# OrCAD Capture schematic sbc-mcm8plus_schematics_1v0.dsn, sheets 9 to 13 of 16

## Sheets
9 04. ENET-RTL8211, ENET1-RGMII: size A3; title: SBC-MCM8PLUS   04. ENET-RTL8211, ENET1-RGMII
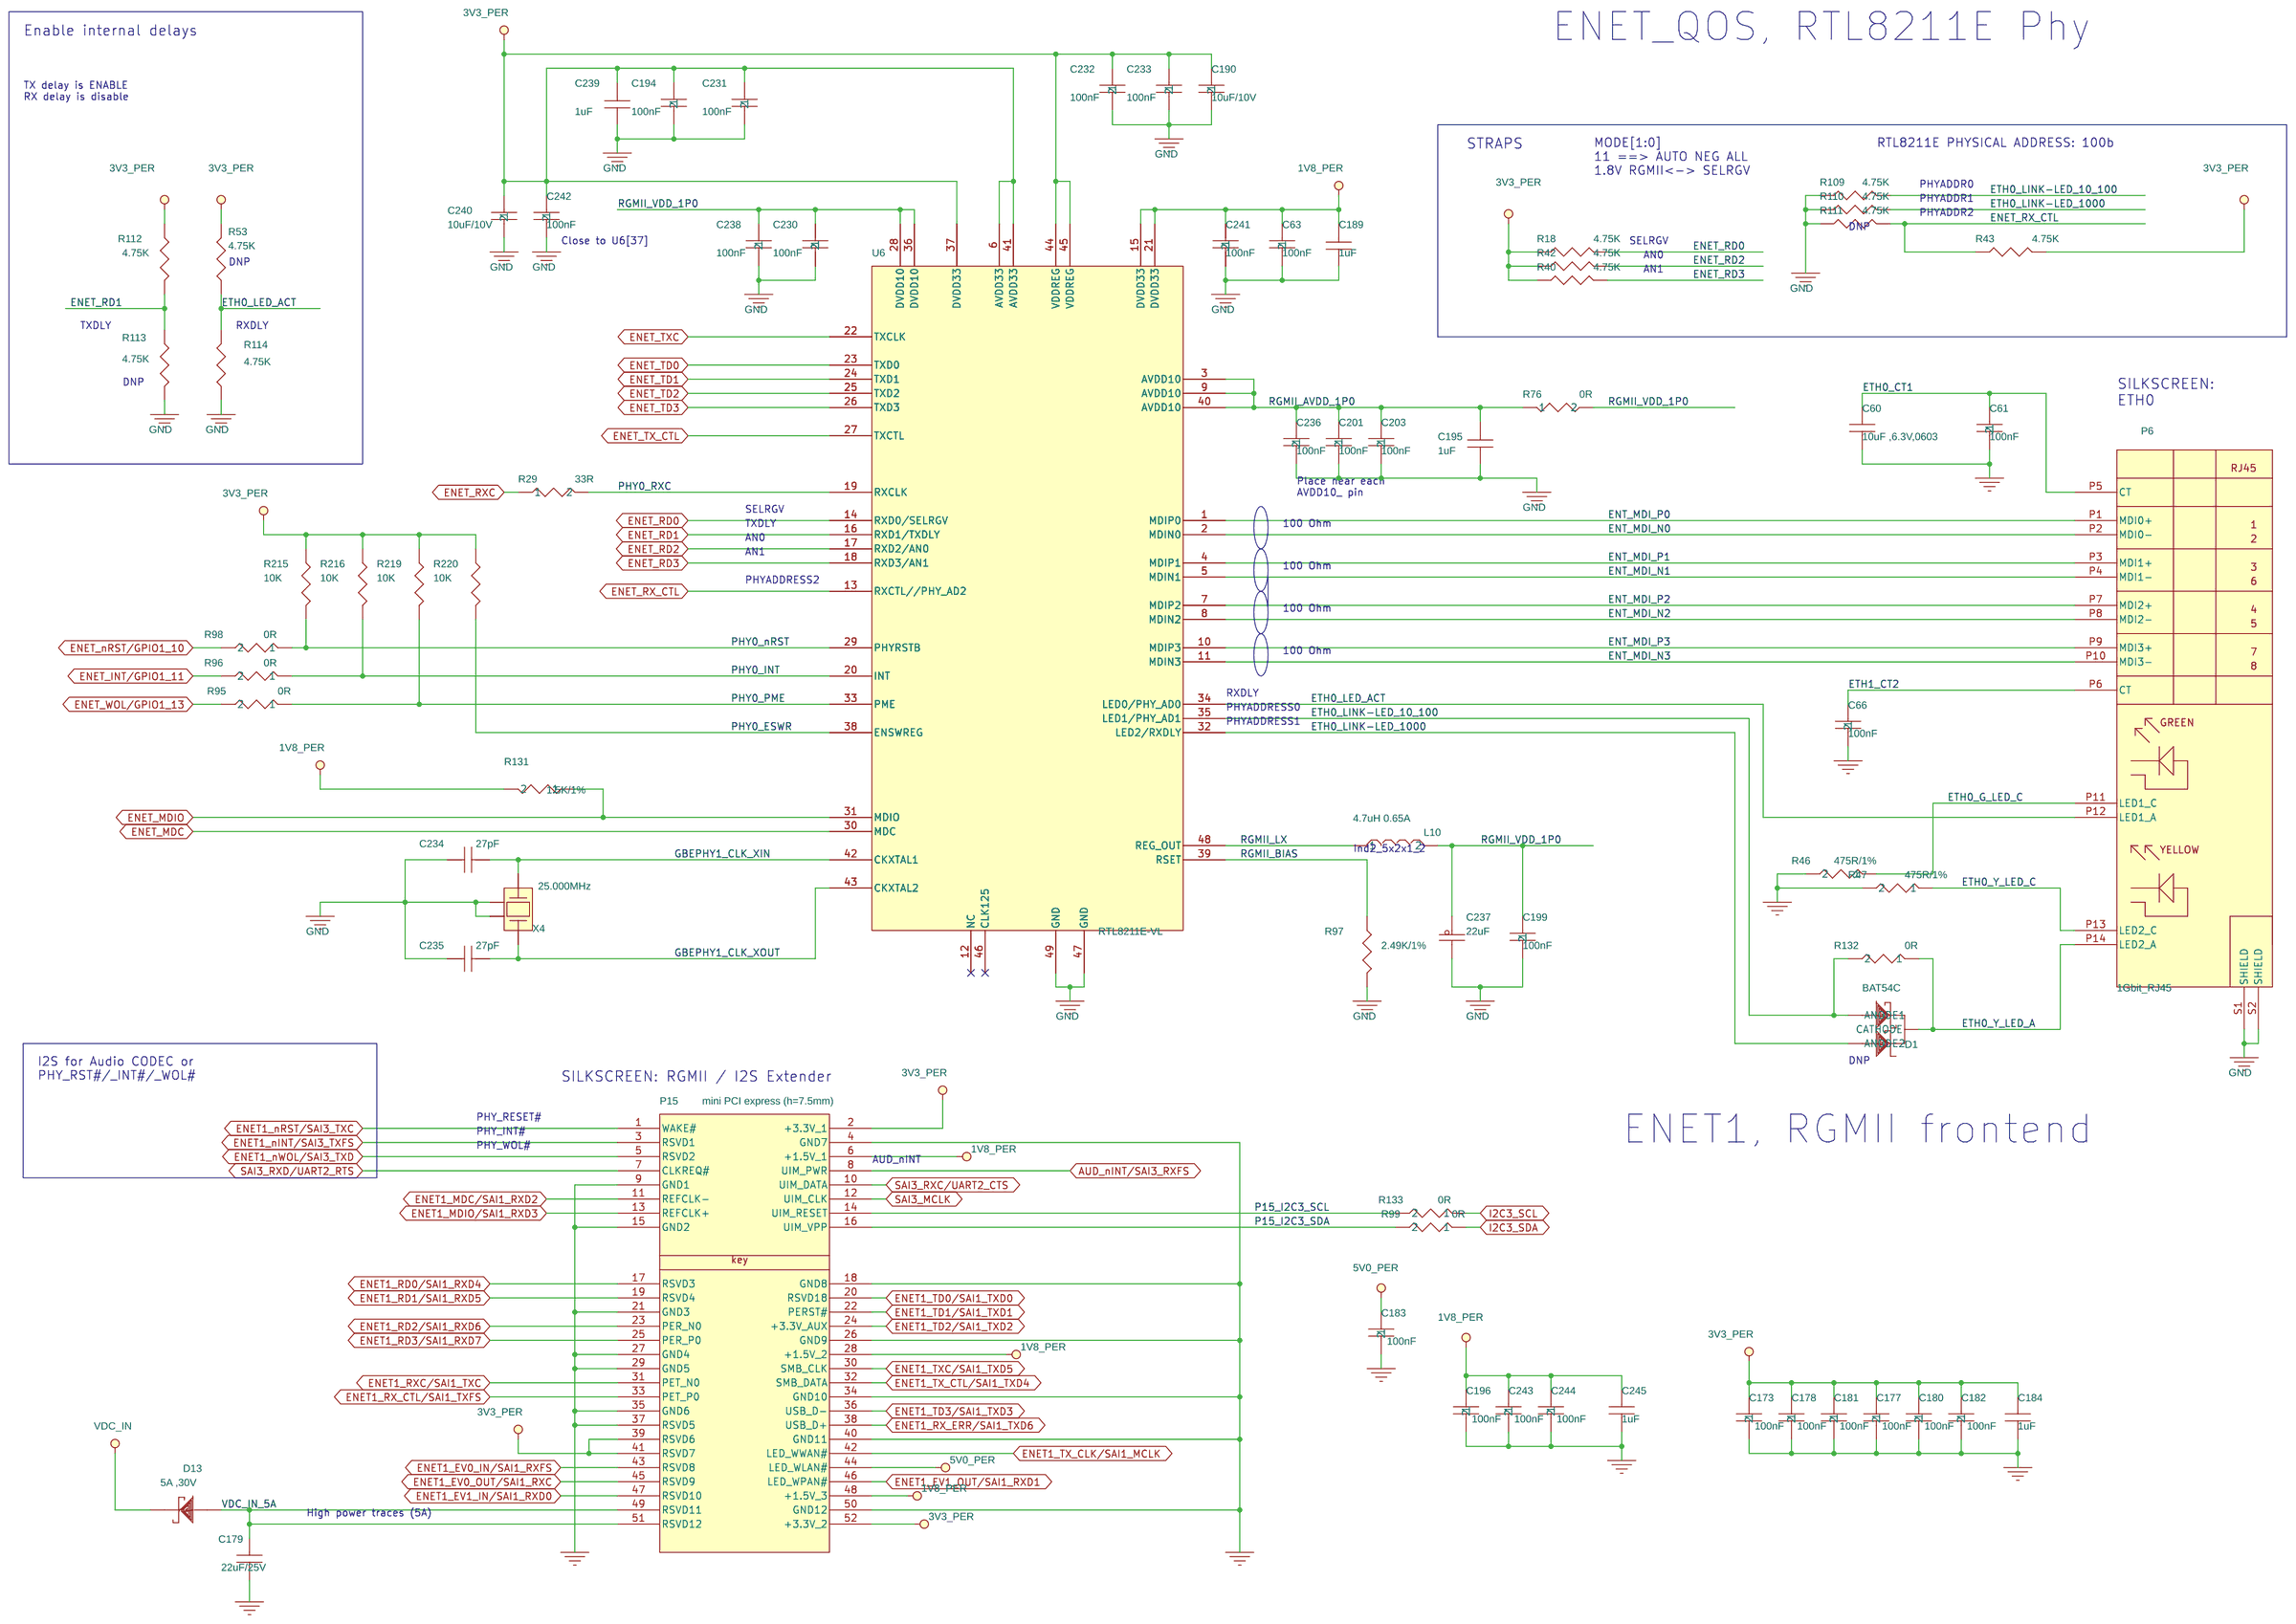
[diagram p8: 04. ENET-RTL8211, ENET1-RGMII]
10 06. JTAG, CAN, GPIO Exp., Misc.: size A2; title: SBC-MCM8PLUS   06. JTAG, CAN, GPIO Exp., Misc.
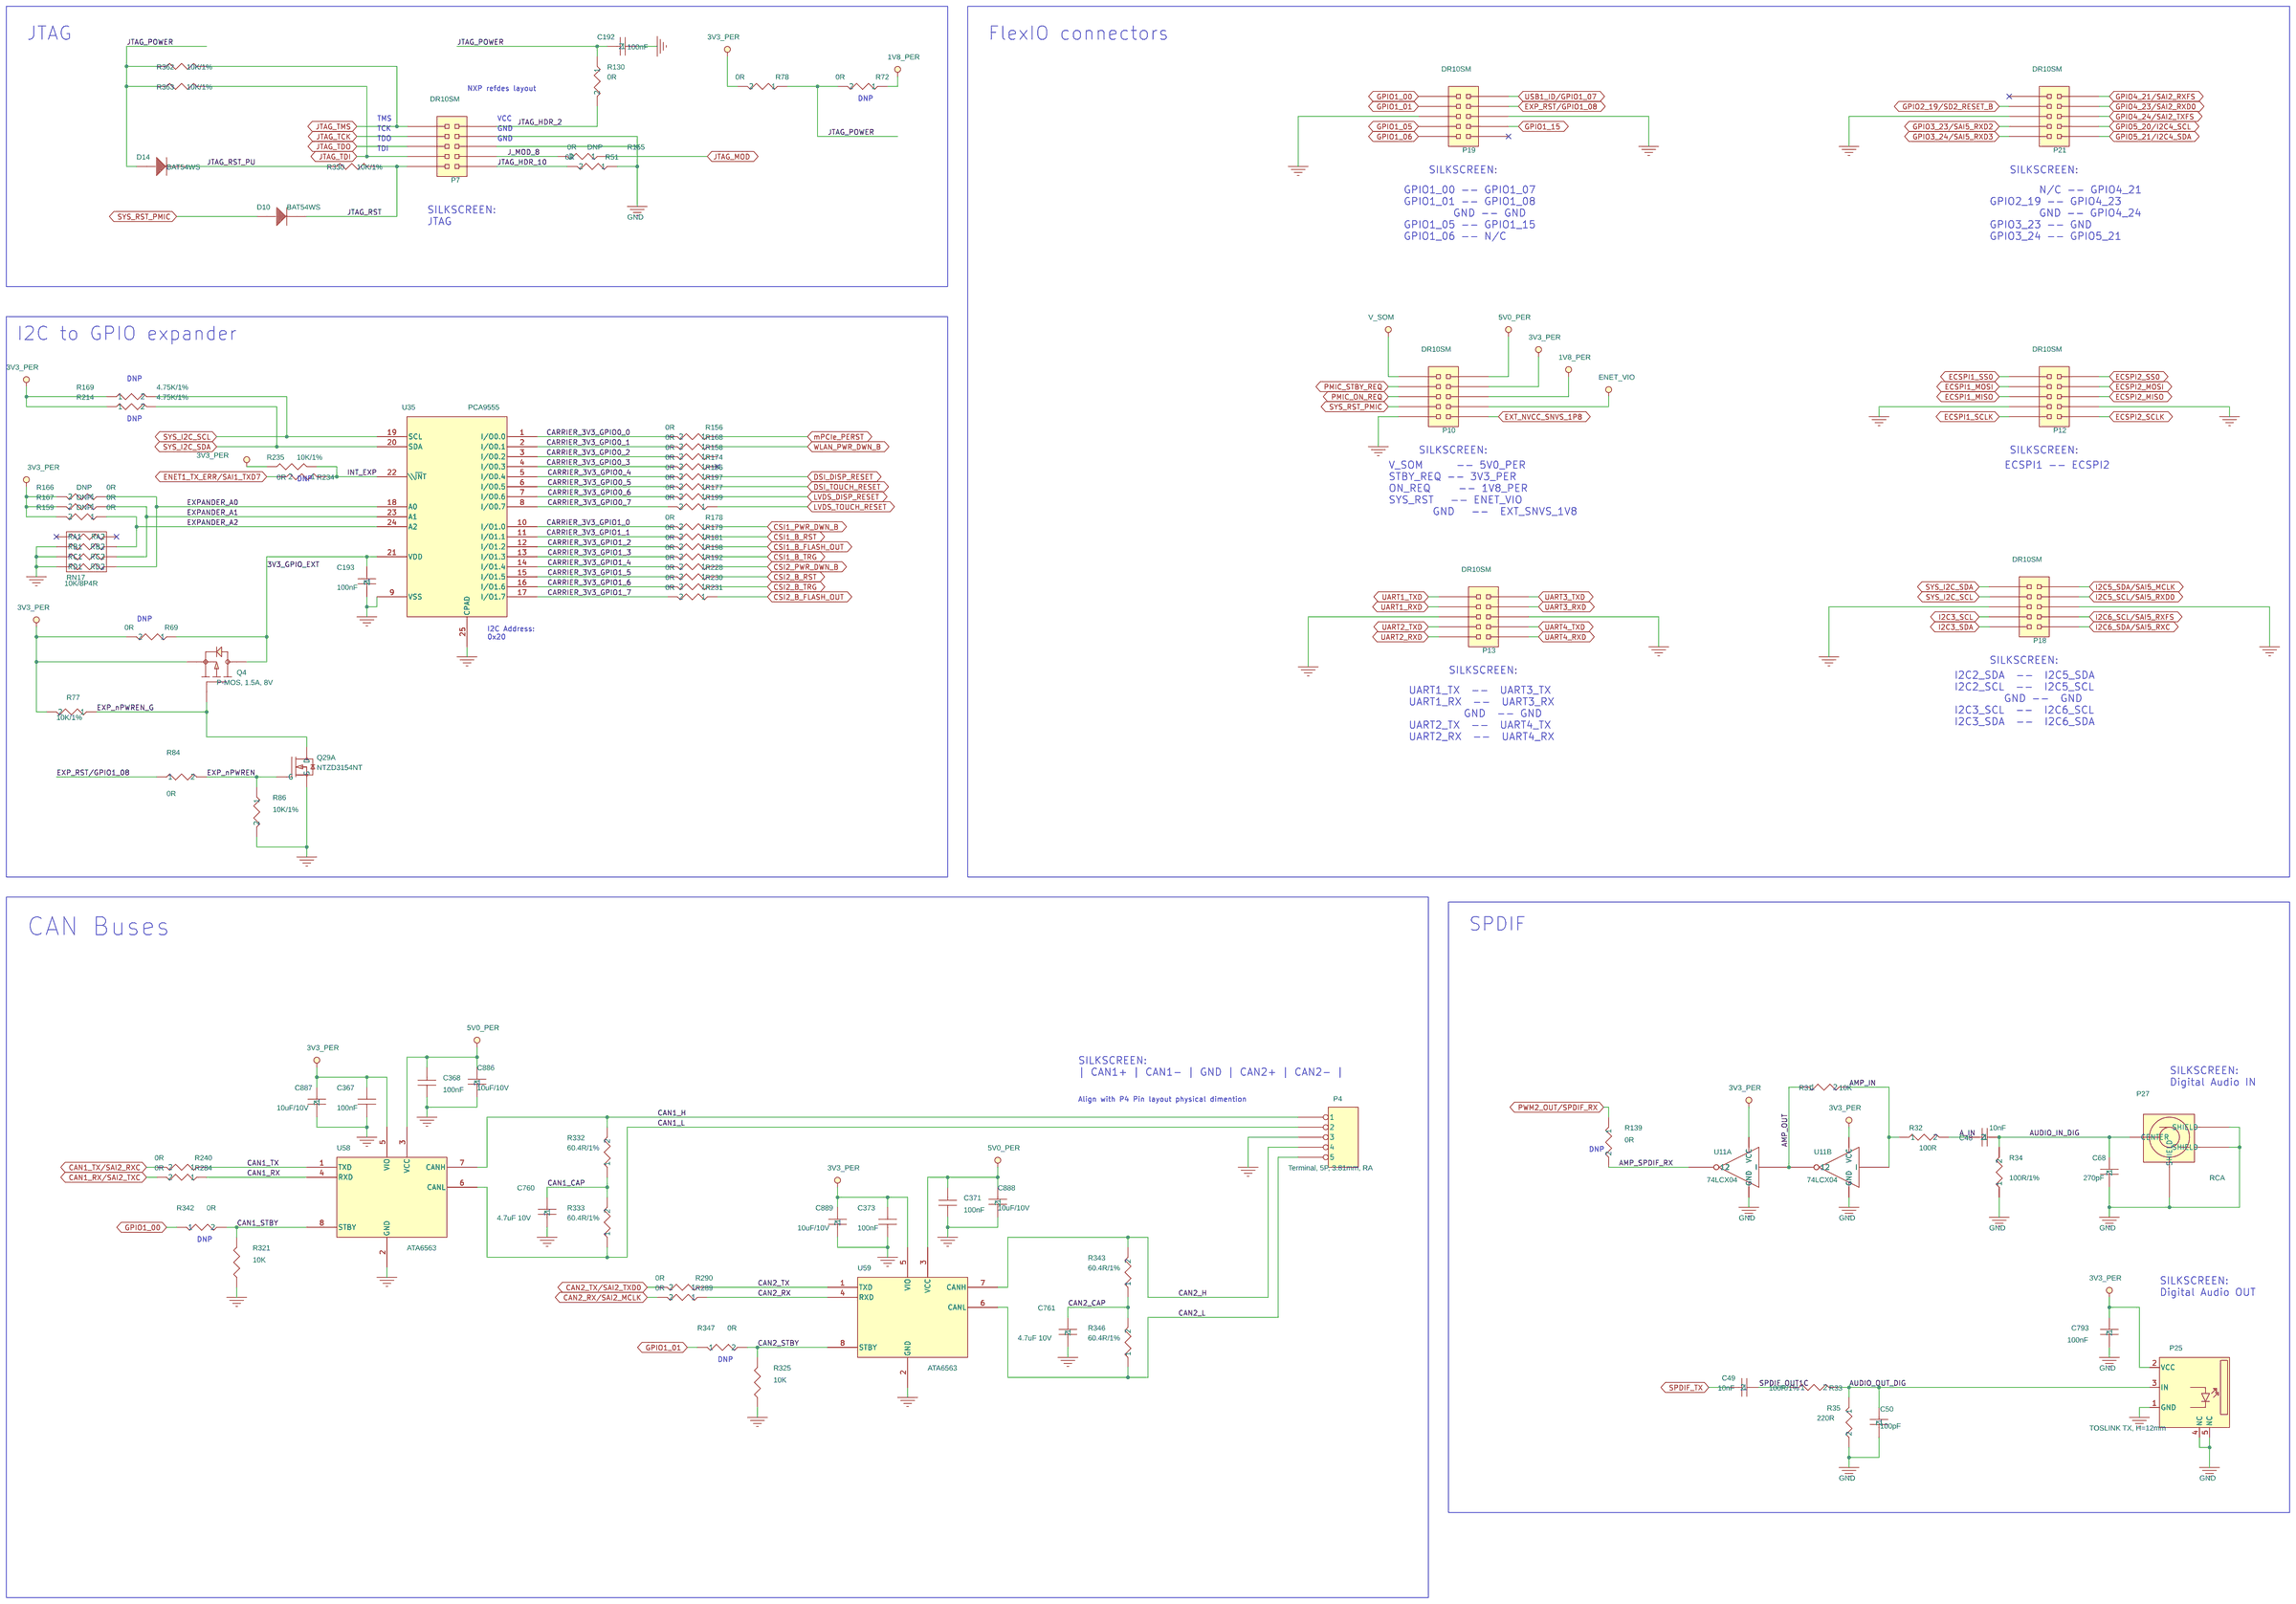
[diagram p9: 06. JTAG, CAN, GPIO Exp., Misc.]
11 07. MIPI-DSI LCD: size A3; title: SBC-MCM8PLUS   07. MIPI-DSI LCD
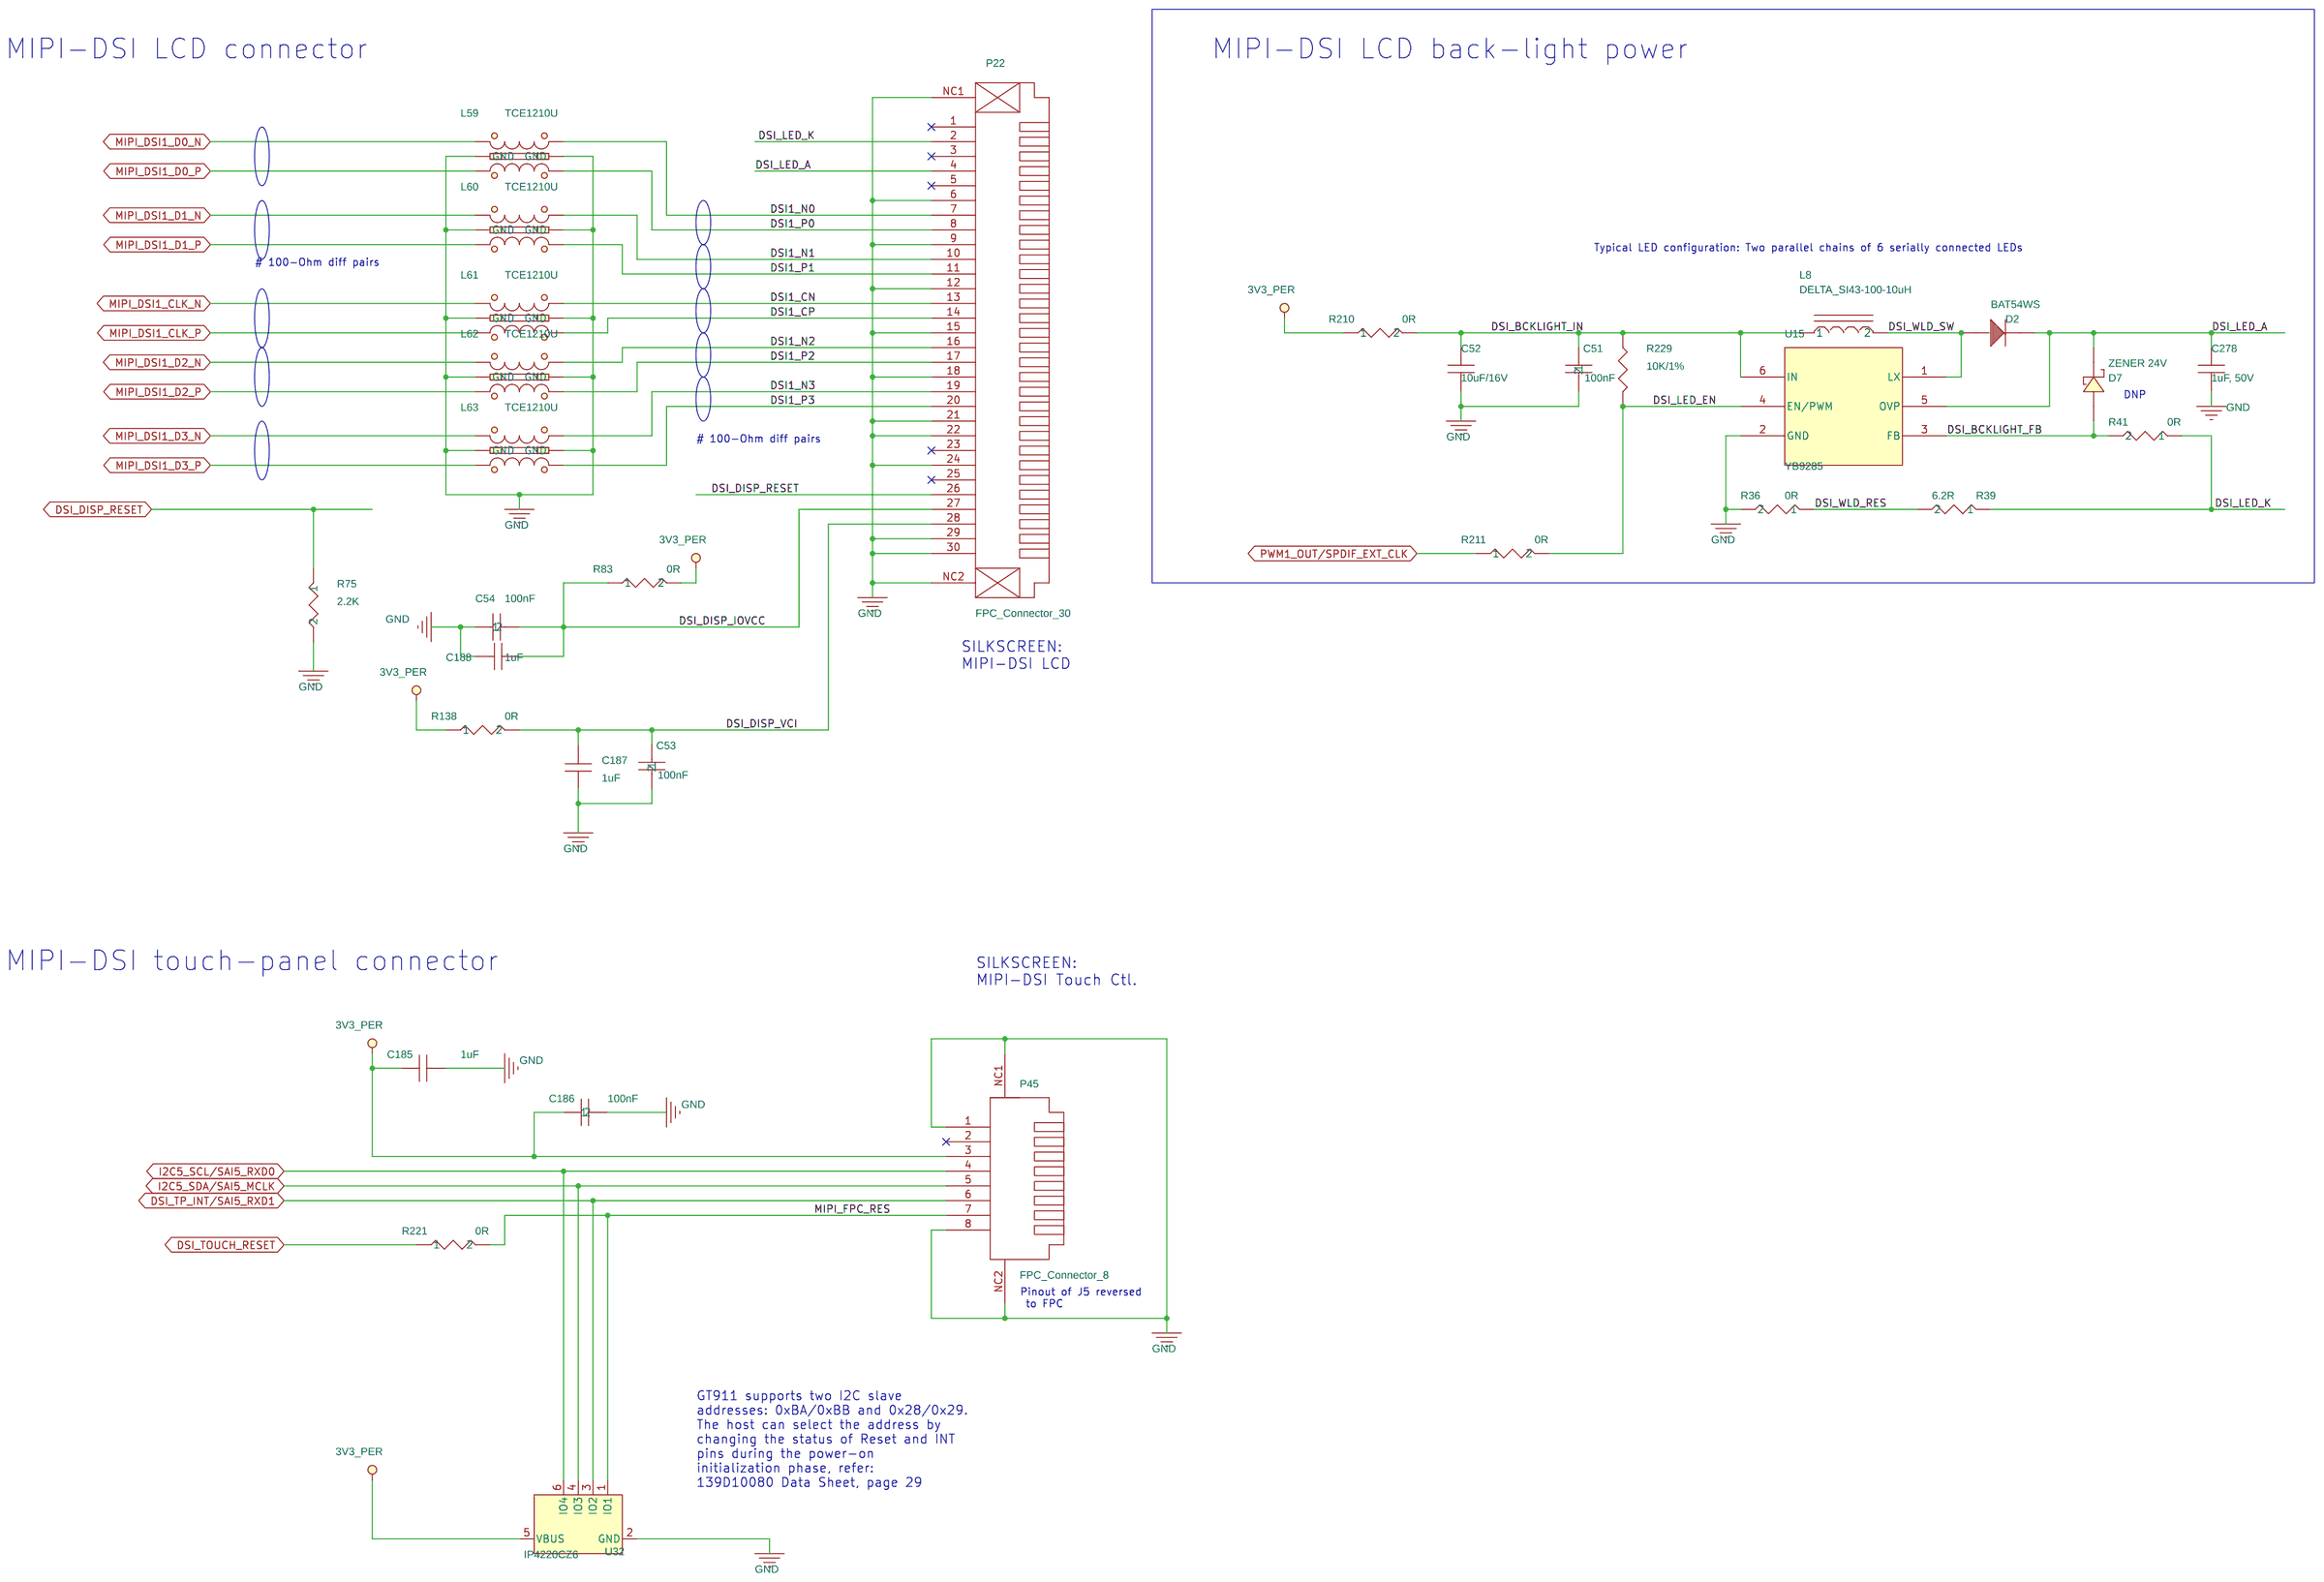
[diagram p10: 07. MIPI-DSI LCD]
12 12. mPCIE Connector: size A3; title: SBC-MCM8PLUS   12. mPCIE Connector
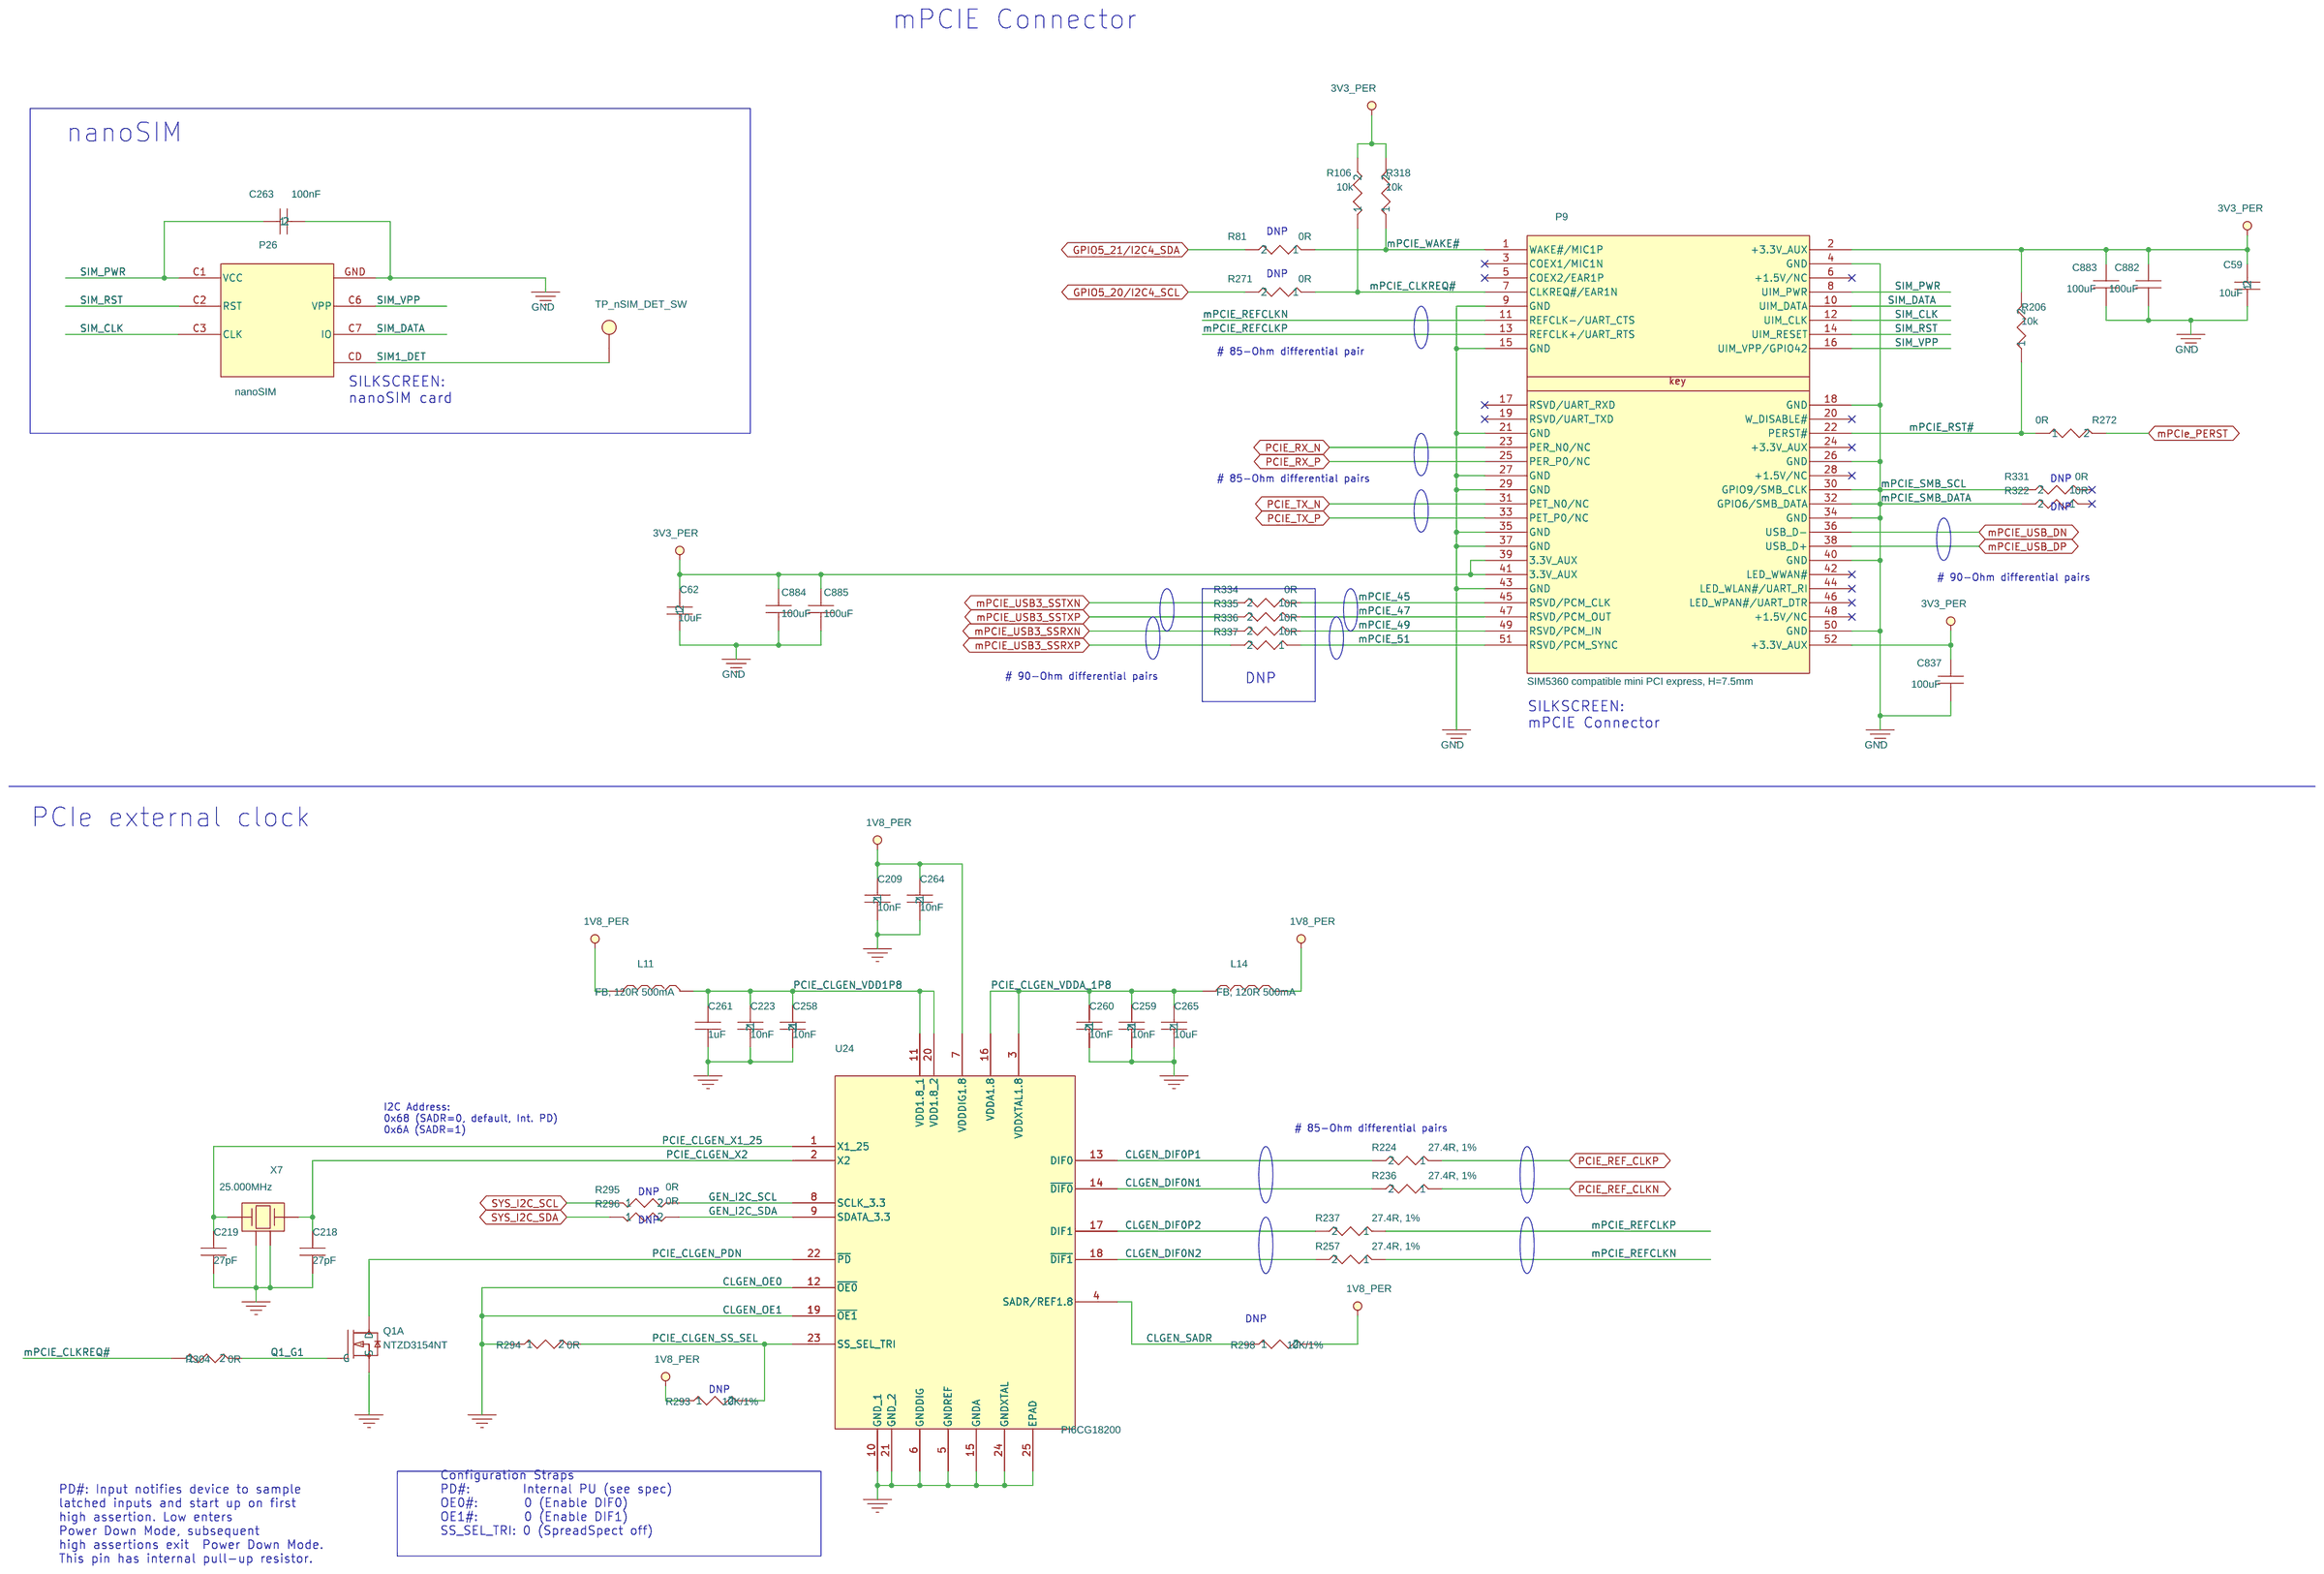
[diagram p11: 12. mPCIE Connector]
13 13. Power: size A3; title: SBC-MCM8PLUS   13. POWER
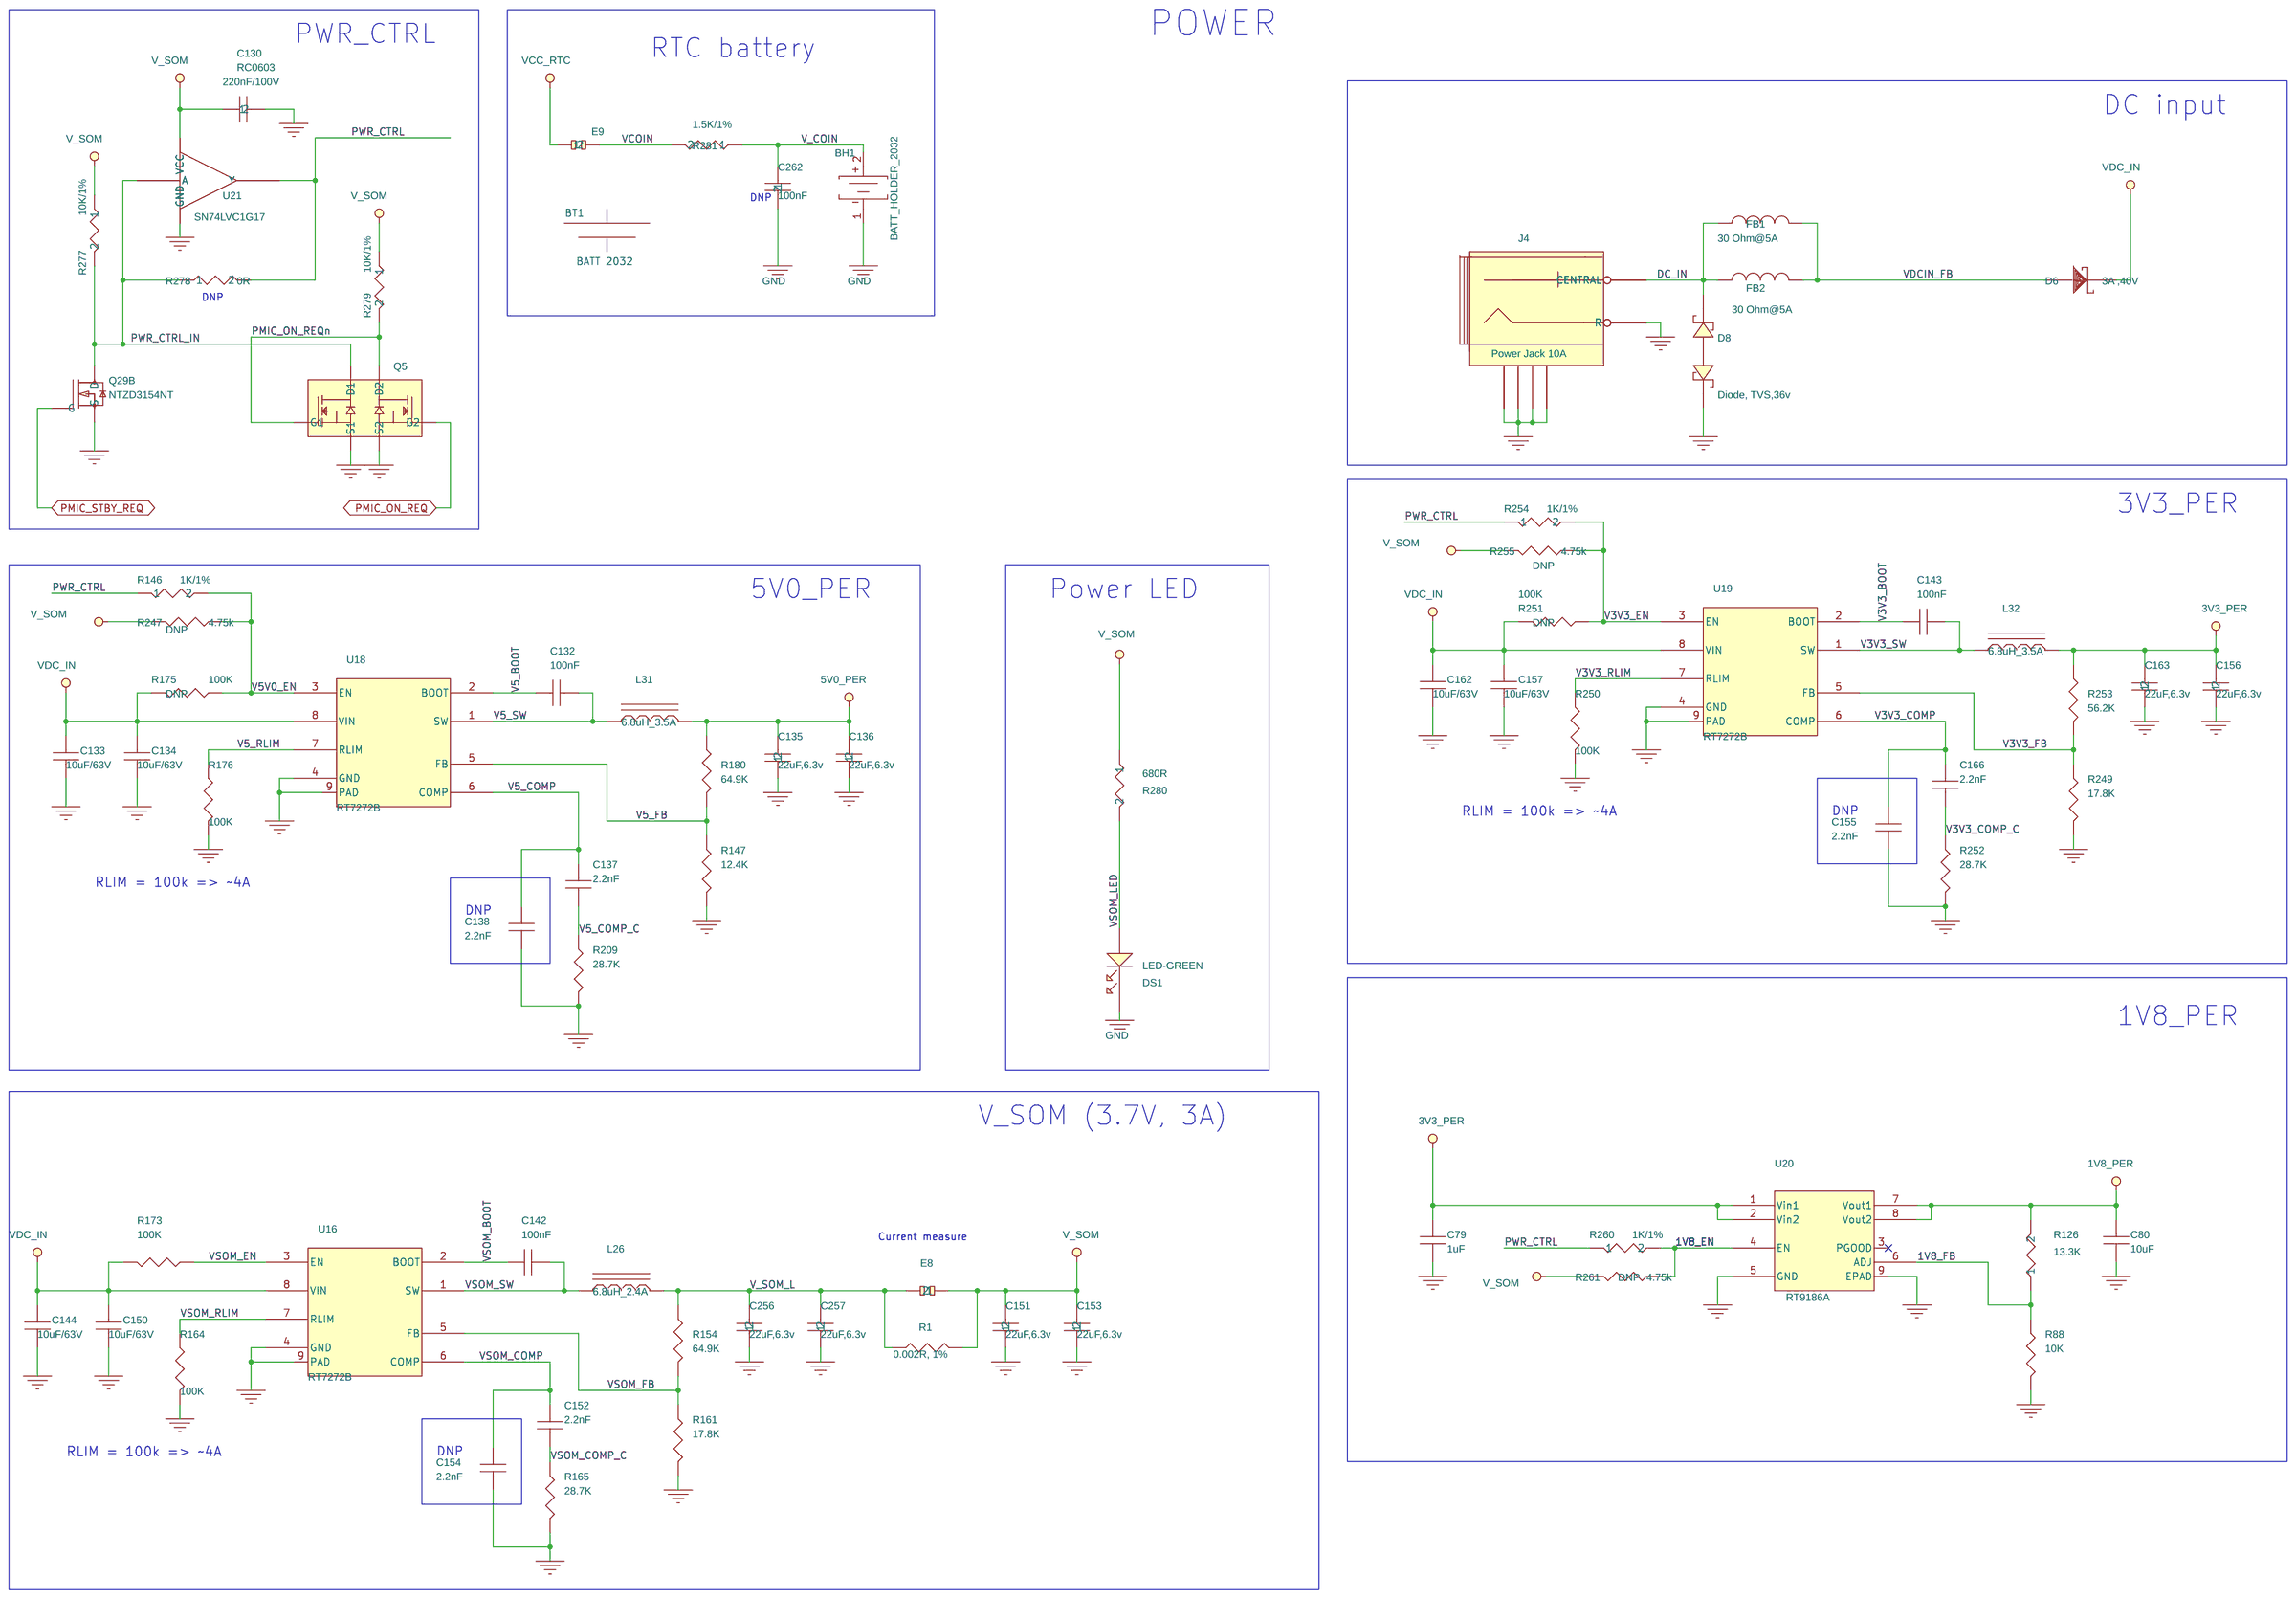
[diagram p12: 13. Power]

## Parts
sheet 04. ENET-RTL8211, ENET1-RGMII
C60  10uF ,6.3V,0603  [RC0603]
C61  100nF  [RC0402]
C63  100nF  [RC0201]
C66  100nF  [RC0402]
C173  100nF  [RC0402]
C177  100nF  [RC0402]
C178  100nF  [RC0402]
C179  22uF/25V  [C0805]
C180  100nF  [RC0402]
C181  100nF  [RC0402]
C182  100nF  [RC0402]
C183  100nF  [RC0402]
C184  1uF  [RC0402]
C189  1uF  [RC0201]
C190  10uF/10V  [RC0402]
C194  100nF  [RC0201]
C195  1uF  [RC0201]
C196  100nF  [RC0402]
C199  100nF  [RC0402]
C201  100nF  [RC0201]
C203  100nF  [RC0201]
C230  100nF  [RC0201]
C231  100nF  [RC0201]
C232  100nF  [RC0201]
C233  100nF  [RC0201]
C234  27pF  [RC0402]
C235  27pF  [RC0402]
C236  100nF  [RC0201]
C237  22uF
C238  100nF  [RC0201]
C239  1uF  [RC0201]
C240  10uF/10V  [RC0402]
C241  100nF  [RC0201]
C242  100nF  [RC0402]
C243  100nF  [RC0402]
C244  100nF  [RC0402]
C245  1uF  [RC0402]
D1  BAT54C  [SOT23]
D13  5A ,30V  [SOD-128]
L10  4.7uH 0.65A  [Ind2_5x2x1_2]
P6  1Gbit_RJ45  [DUSBRJ-1G]
P15  mini PCI express (h=7.5mm)  [MINIPCIE-4]
R18  4.75K  [RC0402]
R29  33R  [RC0201]
R40  4.75K  [RC0402]
R42  4.75K  [RC0402]
R43  4.75K  [RC0402]
R46  475R/1%  [RC0402]
R47  475R/1%  [RC0402]
R53  4.75K  [RC0402]
R76  0R  [RC0402]
R95  0R  [RC0201]
R96  0R  [RC0201]
R97  2.49K/1%  [RC0402]
R98  0R  [RC0201]
R99  0R  [RC0201]
R109  4.75K  [RC0402]
R110  4.75K  [RC0402]
R111  4.75K  [RC0402]
R112  4.75K  [RC0402]
R113  4.75K  [RC0402]
R114  4.75K  [RC0402]
R131  1.5K/1%  [RC0201]
R132  0R  [RC0201]
R133  0R  [RC0201]
R215  10K  [RC0201]
R216  10K  [RC0201]
R219  10K  [RC0201]
R220  10K  [RC0201]
U6  RTL8211E-VL  [MO-220VJJE]
X4  25.000MHz  [OSC3225]
sheet 06. JTAG, CAN, GPIO Exp., Misc.
C48  10nF  [RC0402]
C49  10nF  [RC0402]
C50  100pF  [RC0402]
C68  270pF  [RC0402]
C192  100nF  [RC0402]
C193  100nF  [RC0402]
C367  100nF  [RC0402]
C368  100nF  [RC0402]
C371  100nF  [RC0402]
C373  100nF  [RC0402]
C760  4.7uF 10V  [RC0402]
C761  4.7uF 10V  [RC0402]
C793  100nF  [RC0402]
C886  10uF/10V  [RC0402]
C887  10uF/10V  [RC0402]
C888  10uF/10V  [RC0402]
C889  10uF/10V  [RC0402]
D10  BAT54WS  [SOD-323]
D14  BAT54WS  [SOD-323]
P4  Terminal, 5P, 3.81mm, RA  [TB3.81mmRA-5P]
P7  DR10SM  [2X5SMHDR]
P10  DR10SM  [2X5SMHDR]
P12  DR10SM  [2X5SMHDR]
P13  DR10SM  [2X5SMHDR]
P18  DR10SM  [2X5SMHDR]
P19  DR10SM  [2X5SMHDR]
P21  DR10SM  [2X5SMHDR]
P25  TOSLINK TX, H=12mm  [FO10X12-12]
P27  RCA
Q4  P-MOS, 1.5A, 8V  [SOT23]
Q29  NTZD3154NT  [SOT-563-6]  (sections A,B)
R31  10K  [RC0402]
R32  100R  [RC0402]
R33  100R/1%  [RC0402]
R34  100R/1%  [RC0402]
R35  220R  [RC0402]
R51  0R  [RC0402]
R69  0R  [RC0402]
R72  0R  [RC0402]
R77  10K/1%  [RC0402]
R78  0R  [RC0402]
R84  0R  [RC0402]
R86  10K/1%  [RC0402]
R130  0R  [RC0402]
R139  0R  [RC0402]
R155  0R  [RC0402]
R156  0R  [RC0402]
R158  0R  [RC0402]
R159  0R  [RC0402]
R166  0R  [RC0402]
R167  0R  [RC0402]
R168  0R  [RC0402]
R169  4.75K/1%  [RC0402]
R174  0R  [RC0402]
R177  0R  [RC0402]
R178  0R  [RC0402]
R179  0R  [RC0402]
R181  0R  [RC0402]
R192  0R  [RC0402]
R196  0R  [RC0402]
R197  0R  [RC0402]
R198  0R  [RC0402]
R199  0R  [RC0402]
R214  4.75K/1%  [RC0402]
R228  0R  [RC0402]
R230  0R  [RC0402]
R231  0R  [RC0402]
R234  0R  [RC0402]
R235  10K/1%  [RC0402]
R240  0R  [RC0402]
R284  0R  [RC0402]
R289  0R  [RC0402]
R290  0R  [RC0402]
R321  10K  [RC0402]
R325  10K  [RC0402]
R330  10K/1%  [RC0402]
R332  60.4R/1%  [RC0402]
R333  60.4R/1%  [RC0402]
R342  0R  [RC0402]
R343  60.4R/1%  [RC0402]
R346  60.4R/1%  [RC0402]
R347  0R  [RC0402]
R362  10K/1%  [RC0402]
R363  10K/1%  [RC0402]
RN17  10K/8P4R  [RESNET8P0805]
U11  74LCX04  [TSSOP-14]  (sections A,B)
U35  PCA9555  [QFN4x4-24]
U58  ATA6563  [SOI8-150]
U59  ATA6563  [SOI8-150]
sheet 07. MIPI-DSI LCD
C51  100nF  [RC0402]
C52  10uF/16V  [RC0603]
C53  100nF  [RC0402]
C54  100nF  [RC0402]
C185  1uF  [RC0402]
C186  100nF  [RC0402]
C187  1uF  [RC0402]
C188  1uF  [RC0402]
C278  1uF, 50V  [RC0603]
D2  BAT54WS  [SOD-323]
D7  ZENER 24V  [SOD-123]
L8  DELTA_SI43-100-10uH  [IND4x4x2_5]
L59  TCE1210U  [EMI1012-ESD]
L60  TCE1210U  [EMI1012-ESD]
L61  TCE1210U  [EMI1012-ESD]
L62  TCE1210U  [EMI1012-ESD]
L63  TCE1210U  [EMI1012-ESD]
P22  FPC_Connector_30  [FPC_30]
P45  FPC_Connector_8  [FPC_8]
R36  0R  [RC0402]
R39  6.2R  [RC0402]
R41  0R  [RC0402]
R75  2.2K  [RC0402]
R83  0R  [RC0402]
R138  0R  [RC0402]
R210  0R  [RC0402]
R211  0R  [RC0402]
R221  0R  [RC0402]
R229  10K/1%  [RC0402]
U15  YB9285  [SOT23-6L]
U32  IP4220CZ6  [SOT23-6L]
sheet 12. mPCIE Connector
C59  10uF  [RC0402]
C62  10uF  [RC0402]
C209  10nF  [RC0402]
C218  27pF  [RC0402]
C219  27pF  [RC0402]
C223  10nF  [RC0402]
C258  10nF  [RC0402]
C259  10nF  [RC0402]
C260  10nF  [RC0402]
C261  1uF  [RC0402]
C263  100nF  [RC0402]
C264  10nF  [RC0402]
C265  10uF  [RC0402]
C837  100uF  [C1206]
C882  100uF  [C1206]
C883  100uF  [C1206]
C884  100uF  [C1206]
C885  100uF  [C1206]
L11  FB, 120R 500mA  [FB0402]
L14  FB, 120R 500mA  [FB0402]
P9  SIM5360 compatible mini PCI express, H=7.5mm  [MINIPCIE-4]
P26  nanoSIM  [SKT-NanoSIM-CD-SM]
Q1  NTZD3154NT  [SOT-563-6]  (section A)
R81  0R  [RC0402]
R106  10k  [RC0402]
R206  10k  [RC0402]
R224  27.4R, 1%  [RC0402]
R236  27.4R, 1%  [RC0402]
R237  27.4R, 1%  [RC0402]
R257  27.4R, 1%  [RC0402]
R271  0R  [RC0402]
R272  0R  [RC0402]
R293  10K/1%  [RC0402]
R294  0R  [RC0402]
R295  0R  [RC0402]
R296  0R  [RC0402]
R298  10K/1%  [RC0402]
R304  0R  [RC0402]
R318  10k  [RC0402]
R322  0R  [RC0402]
R331  0R  [RC0402]
R334  0R  [RC0402]
R335  0R  [RC0402]
R336  0R  [RC0402]
R337  0R  [RC0402]
TP_nSIM_DET_SW  TP  [TP_TH_0p5mm]
U24  PI6CG18200  [MO-220VGGD-8]
X7  25.000MHz  [OSC3225]
sheet 13. Power
BH1  BATT_HOLDER_2032  [BATTH20MM]
BT1  BATT 2032
C79  1uF  [RC0402]
C80  10uF  [C0603-08]
C130  220nF/100V  [RC0603]
C132  100nF  [RC0402]
C133  10uF/63V  [C1210H2_5]
C134  10uF/63V  [C1210H2_5]
C135  22uF,6.3v  [RC0603]
C136  22uF,6.3v  [RC0603]
C137  2.2nF  [RC0402]
C138  2.2nF  [RC0402]
C142  100nF  [RC0402]
C143  100nF  [RC0402]
C144  10uF/63V  [C1210H2_5]
C150  10uF/63V  [C1210H2_5]
C151  22uF,6.3v  [RC0603]
C152  2.2nF  [RC0402]
C153  22uF,6.3v  [RC0603]
C154  2.2nF  [RC0402]
C155  2.2nF  [RC0402]
C156  22uF,6.3v  [RC0603]
C157  10uF/63V  [C1210H2_5]
C162  10uF/63V  [C1210H2_5]
C163  22uF,6.3v  [RC0603]
C166  2.2nF  [RC0402]
C256  22uF,6.3v  [RC0603]
C257  22uF,6.3v  [RC0603]
C262  100nF  [RC0402]
D6  3A ,40V  [DO-214AC]
D8  Diode, TVS,36v  [SOD-323]
DS1  LED-GREEN  [LED-1206]
E8  HDR1X2  [1X2THHDR]
E9  HDR1X2  [1X2THHDR]
FB1  30 Ohm@5A  [FB0603]
FB2  30 Ohm@5A  [FB0603]
J4  Power Jack 10A  [PJ-0810-TH]
L26  6.8uH_2.4A  [IND6x5_5x3]
L31  6.8uH_3.5A  [IND6x5_5x3]
L32  6.8uH_3.5A  [IND6x5_5x3]
Q5  0.5A,20V,Vgs max 6V  [SOT-563-6]
R1  0.002R, 1%  [R1206]
R88  10K  [RC0402]
R126  13.3K  [RC0402]
R146  1K/1%  [RC0402]
R147  12.4K  [RC0402]
R154  64.9K  [RC0402]
R161  17.8K  [RC0402]
R164  100K  [RC0402]
R165  28.7K  [RC0402]
R173  100K  [RC0402]
R175  100K  [RC0402]
R176  100K  [RC0402]
R180  64.9K  [RC0402]
R209  28.7K  [RC0402]
R247  4.75k  [RC0402]
R249  17.8K  [RC0402]
R250  100K  [RC0402]
R251  100K  [RC0402]
R252  28.7K  [RC0402]
R253  56.2K  [RC0402]
R254  1K/1%  [RC0402]
R255  4.75k  [RC0402]
R260  1K/1%  [RC0402]
R261  4.75k  [RC0402]
R277  10K/1%  [RC0402]
R278  0R  [RC0402]
R279  10K/1%  [RC0402]
R280  680R  [RC0402]
R281  1.5K/1%  [RC0402]
U16  RT7272B  [PSOP-8-2X2]
U18  RT7272B  [PSOP-8-2X2]
U19  RT7272B  [PSOP-8-2X2]
U20  RT9186A  [DFN3x3-8]
U21  SN74LVC1G17

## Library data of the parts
C60 = Cap.,10uF,6.3V,0603,X5R: CLABCONF0: = SBC-MCM8PLUS
C61 = 100nF,_10V,_X7R,_10%,_0402_18: CLABCONF0: = SBC-MCM8PLUS
C63 = 100nF,_10V,_X7R,_10%,_0402_11: CLABCONF0: = SBC-MCM8PLUS; P/N: 151B104B0S
C66 = 100nF,_10V,_X7R,_10%,_0402_9: CLABCONF0: = SBC-MCM8PLUS
C173 = 100nF,_10V,_X7R,_10%,_0402_14: CLABCONF0: = SBC-MCM8PLUS
C177 = 100nF,_10V,_X7R,_10%,_0402_20: CLABCONF0: = SBC-MCM8PLUS
C178 = 100nF,_10V,_X7R,_10%,_0402_24: CLABCONF0: = SBC-MCM8PLUS
C179 = Cap.,22uF,25V,_0805: CLABCONF0: = SBC-MCM8PLUS
C180 C186 = 100nF,_10V,_X7R,_10%,_0402_2: CLABCONF0: = SBC-MCM8PLUS
C181 = 100nF,_10V,_X7R,_10%,_0402_4: CLABCONF0: = SBC-MCM8PLUS
C182 = 100nF,_10V,_X7R,_10%,_0402_6: CLABCONF0: = SBC-MCM8PLUS
C183 = 100nF,_10V,_X7R,_10%,_0402_13: CLABCONF0: = SBC-MCM8PLUS
C79 C184 C185 C187 C188 C245 C261 = 1uF,X5R,6.3V,0402: CLABCONF0: = SBC-MCM8PLUS
C189 C195 C239 = 1uF,16V,0402: CLABCONF0: = SBC-MCM8PLUS; P/N: 151B105B0S
C190 C886 = 10uF_10V_20%_0402: CLABCONF0: = SBC-MCM8PLUS
C194 = 100nF,_10V,_X7R,_10%,_0402_15: CLABCONF0: = SBC-MCM8PLUS; P/N: 151B104B0S
C196 = 100nF,_10V,_X7R,_10%,_0402_16: CLABCONF0: = SBC-MCM8PLUS
C199 = 100nF,_10V,_X7R,_10%,_0402_10: CLABCONF0: = SBC-MCM8PLUS; P/N: 151B10400S
C201 = 100nF,_10V,_X7R,_10%,_0402_19: CLABCONF0: = SBC-MCM8PLUS; P/N: 151B104B0S
C203 = 100nF,_10V,_X7R,_10%,_0402_23: CLABCONF0: = SBC-MCM8PLUS; P/N: 151B104B0S
C230 = 100nF,_10V,_X7R,_10%,_0402_8: CLABCONF0: = SBC-MCM8PLUS; P/N: 151B104B0S
C231 = 100nF,_10V,_X7R,_10%,_0402_17: CLABCONF0: = SBC-MCM8PLUS; P/N: 151B104B0S
C232 = 100nF,_10V,_X7R,_10%,_0402_5: CLABCONF0: = SBC-MCM8PLUS; P/N: 151B104B0S
C233 = 100nF,_10V,_X7R,_10%,_0402_7: CLABCONF0: = SBC-MCM8PLUS; P/N: 151B104B0S
C218 C219 C234 C235 = 27pF,_50V,_X7R,_10%,_0402: CLABCONF0: = SBC-MCM8PLUS; P/N: 151D27000S
C236 = 100nF,_10V,_X7R,_10%,_0402_3: CLABCONF0: = SBC-MCM8PLUS; P/N: 151B104B0S
C237 = CAP_NP_3: CAP CER 22uF 10V 20% X5R 0603; CLABCONF0: = SBC-MCM8PLUS; FPLIST: CC0603_OV,CC0603,0603_CC; HEIGHT: 1MM; P/N: 151B22610S; Package Size: 0603; ROHS: Yes; SIGNAL_MODEL: DEFAULT_CAPACITOR_2.2e+07pF_2_1; Tolerance: 20%; VOLTAGE: 6.3V
C238 = 100nF,_10V,_X7R,_10%,_0402_1: CLABCONF0: = SBC-MCM8PLUS; P/N: 151B10400S
C240 C888 = 10uF_10V_20%_0402_1: CLABCONF0: = SBC-MCM8PLUS
C241 = 100nF,_10V,_X7R,_10%,_0402_12: CLABCONF0: = SBC-MCM8PLUS; P/N: 151B104B0S
C242 = 100nF,_10V,_X7R,_10%,_0402_22: CLABCONF0: = SBC-MCM8PLUS; P/N: 151B10400S
C243 = 100nF,_10V,_X7R,_10%,_0402_21: CLABCONF0: = SBC-MCM8PLUS
C53 C193 C244 C263 = 100nF,_10V,_X7R,_10%,_0402: CLABCONF0: = SBC-MCM8PLUS
D1 = BAT54C: CLABCONF0: DNP
D13 = Diode_Shotky,5A,30V: CLABCONF0: = SBC-MCM8PLUS
L10 = Ind,_4.7uH,_30%,_1.2A,_0.07_ohm: CLABCONF0: = SBC-MCM8PLUS; P/N: 147A4R704S
P6 = Con_0.,1GBit_RJ45,_short: CLABCONF0: = SBC-MCM8PLUS
P15 = mini_PCIe_0: CLABCONF0: = SBC-MCM8PLUS; P/N: 182K05202S
R18 R40 R42 R43 R109 R110 R112 R114 = RESISTOR: CLABCONF0: = SBC-MCM8PLUS; P/N: 161C47511S
R29 = 33R,5%,0402,1_16W_0: CLABCONF0: = SBC-MCM8PLUS; P/N: 161B33R01S
R46 = 475R_1%,_0402_1: CLABCONF0: = SBC-MCM8PLUS
R47 = 475R_1%,_0402: CLABCONF0: = SBC-MCM8PLUS
R53 R111 R113 = RESISTOR: CLABCONF0: DNP; P/N: 161C47511S
R76 = 0R,_0402_0_1: CLABCONF0: = SBC-MCM8PLUS; P/N: 161C00005S
R95 = 0R,_0402_0_3: CLABCONF0: = SBC-MCM8PLUS; P/N: 161B00001S
R96 = 0R,_0402_0_5: CLABCONF0: = SBC-MCM8PLUS; P/N: 161B00001S
R97 = 2.37K_1%,_0402: CLABCONF0: = SBC-MCM8PLUS; P/N: 161C24911S
R98 = 0R,_0402_0: CLABCONF0: = SBC-MCM8PLUS; P/N: 161B00001S
R99 = 0R,_0402_0_2: CLABCONF0: = SBC-MCM8PLUS; P/N: 161B00001S
R131 = 1.5K_1%,_0402: CLABCONF0: = SBC-MCM8PLUS; P/N: 161B15011S
R132 = 0R,_0402_0_6: CLABCONF0: = SBC-MCM8PLUS; P/N: 161B00001S
R133 = 0R,_0402_0_4: CLABCONF0: = SBC-MCM8PLUS; P/N: 161B00001S
R215 = 10K,_1%,_0201,_1_20W_3: CLABCONF0: = SBC-MCM8PLUS
R216 = 10K,_1%,_0201,_1_20W: CLABCONF0: = SBC-MCM8PLUS
R219 = 10K,_1%,_0201,_1_20W_1: CLABCONF0: = SBC-MCM8PLUS
R220 = 10K,_1%,_0201,_1_20W_2: CLABCONF0: = SBC-MCM8PLUS
U6 = RTL8211D_0: CLABCONF0: = SBC-MCM8PLUS; P/N: 116A00570S
X4 X7 = XTAL,_25.000Mhz,_3x5mm: CLABCONF0: = SBC-MCM8PLUS; P/N: 141B25603I
C48 = 10nF,_25V,_X7R,_10%,_0402_1: CLABCONF0: = SBC-MCM8PLUS
C49 C209 = 10nF,_25V,_X7R,_10%,_0402: CLABCONF0: = SBC-MCM8PLUS
C50 = 100pF,_50V,_NPO,_5%,_0402: CLABCONF0: = SBC-MCM8PLUS
C68 = 270pF,_50V,_X7R,_5%,_0402: CLABCONF0: = SBC-MCM8PLUS
C54 C192 = 100nF,_10V,_X7R,_10%,_0402_1: CLABCONF0: = SBC-MCM8PLUS
C367 C368 C371 C373 = 100nF,_10V,_X7R,_10%,_0402_0: CLABCONF0: = SBC-MCM8PLUS
C760 = 4.7uF_0402_10V_20%_1: CLABCONF0: = SBC-MCM8PLUS
C761 = 4.7uF_0402_10V_20%: CLABCONF0: = SBC-MCM8PLUS
C793 = 15pF,_50V,_NPO,_5%,_0402: CLABCONF0: = SBC-MCM8PLUS; P/N: 151B10400S
C887 = 10uF_10V_20%_0402_2: CLABCONF0: = SBC-MCM8PLUS
C889 = 10uF_10V_20%_0402_3: CLABCONF0: = SBC-MCM8PLUS
D2 D10 D14 = BAT54WS_0: CLABCONF0: = SBC-MCM8PLUS
P4 = Terminal,_5P,_3.81mm,_RA: CLABCONF0: = SBC-MCM8PLUS
P7 P10 P12 P13 P18 P19 P21 = HDR_2x5_100MIL_SMT: CLABCONF0: = SBC-MCM8PLUS; P/N: 190C01000S
P25 = TOSLINK_TX: CLABCONF0: = SBC-MCM8PLUS; P/N: 138E10030
P27 = RCA: CLABCONF0: = SBC-MCM8PLUS; P/N: 180K00401
Q4 = P-MOS,_1.5A,_8V: CLABCONF0: = SBC-MCM8PLUS
Q1 Q29 = N-MOSFET_Dual: CLABCONF0: = SBC-MCM8PLUS; P/N: 131D31540S
R31 = 10K,1%,0402,1_16W_2: CLABCONF0: = SBC-MCM8PLUS
R32 = 100R,1%,0402,1_16W_1: CLABCONF0: = SBC-MCM8PLUS
R33 = 100R,1%,0402,1_16W_2: CLABCONF0: = SBC-MCM8PLUS
R34 = 100R,1%,0402,1_16W: CLABCONF0: = SBC-MCM8PLUS
R35 = 220R,5%,0402,1_16W: CLABCONF0: = SBC-MCM8PLUS
R51 R210 = 0R,_0402_1: CLABCONF0: = SBC-MCM8PLUS
R69 = 0R,_0402_1_11: CLABCONF0: DNP
R72 = 0R,_0402_1_20: CLABCONF0: DNP
R77 R279 = 10K,1%,0402,1_16W: CLABCONF0: = SBC-MCM8PLUS
R78 = 0R,_0402_1_24: CLABCONF0: = SBC-MCM8PLUS
R84 = 0R,_0402_1_15: CLABCONF0: = SBC-MCM8PLUS
R86 R277 = 10K,1%,0402,1_16W_1: CLABCONF0: = SBC-MCM8PLUS
R130 = 0R,_0402_1_5: CLABCONF0: = SBC-MCM8PLUS
R139 = 0R,_0402_0_1: CLABCONF0: DNP
R155 = 0R,_0402_1_13: CLABCONF0: DNP
R156 = 0R,_0402_1_26: CLABCONF0: = SBC-MCM8PLUS
R158 = 0R,_0402_1_8: CLABCONF0: = SBC-MCM8PLUS
R159 = 0R,_0402_1_14: CLABCONF0: DNP
R166 = 0R,_0402_1_31: CLABCONF0: DNP
R167 = 0R,_0402_1_29: CLABCONF0: DNP
R168 = 0R,_0402_1_22: CLABCONF0: = SBC-MCM8PLUS
R169 = 4_0.75K,1%,0402,1_16W: CLABCONF0: DNP
R174 = 0R,_0402_1_17: CLABCONF0: = SBC-MCM8PLUS
R177 = 0R,_0402_1_27: CLABCONF0: = SBC-MCM8PLUS
R178 = 0R,_0402_1_4: CLABCONF0: = SBC-MCM8PLUS
R179 = 0R,_0402_1_1: CLABCONF0: = SBC-MCM8PLUS
R181 = 0R,_0402_1_28: CLABCONF0: = SBC-MCM8PLUS
R192 = 0R,_0402_1_2: CLABCONF0: = SBC-MCM8PLUS
R196 = 0R,_0402_1_3: CLABCONF0: = SBC-MCM8PLUS
R197 = 0R,_0402_1_9: CLABCONF0: = SBC-MCM8PLUS
R198 = 0R,_0402_1_10: CLABCONF0: = SBC-MCM8PLUS
R199 = 0R,_0402_1_19: CLABCONF0: = SBC-MCM8PLUS
R214 = 4_0.75K,1%,0402,1_16W_1: CLABCONF0: DNP
R228 = 0R,_0402_1_30: CLABCONF0: = SBC-MCM8PLUS
R230 = 0R,_0402_1_12: CLABCONF0: = SBC-MCM8PLUS
R231 = 0R,_0402_1_18: CLABCONF0: = SBC-MCM8PLUS
R234 = 0R,_0402_0: CLABCONF0: DNP; P/N: 161C00005S
R235 = 10K,1%,0402,1_16W_0_2: CLABCONF0: = SBC-MCM8PLUS
R240 = 0R,_0402_1_16: CLABCONF0: = SBC-MCM8PLUS
R284 = 0R,_0402_1_21: CLABCONF0: = SBC-MCM8PLUS
R289 = 0R,_0402_1_23: CLABCONF0: = SBC-MCM8PLUS
R290 = 0R,_0402_1_25: CLABCONF0: = SBC-MCM8PLUS
R321 = 10K,1%,0402,1_16W_0_1: CLABCONF0: = SBC-MCM8PLUS
R325 = 10K,1%,0402,1_16W_0_5: CLABCONF0: = SBC-MCM8PLUS
R330 = 10K,1%,0402,1_16W_0_3: CLABCONF0: DNP
R332 = 60.4R_1%,_0402_2: CLABCONF0: = SBC-MCM8PLUS
R333 = 60.4R_1%,_0402_3: CLABCONF0: = SBC-MCM8PLUS
R342 = 0R,_0402_1_6: CLABCONF0: DNP
R343 = 60.4R_1%,_0402: CLABCONF0: = SBC-MCM8PLUS
R346 = 60.4R_1%,_0402_1: CLABCONF0: = SBC-MCM8PLUS
R347 = 0R,_0402_1_7: CLABCONF0: DNP
R362 = 10K,1%,0402,1_16W_0_4: CLABCONF0: DNP
R363 = 10K,1%,0402,1_16W_0: CLABCONF0: DNP
RN17 = RN,10K,8P4R@0805: CLABCONF0: = SBC-MCM8PLUS
U11 = 74LCX04_sgl_gate_TSSOP-14: CLABCONF0: = SBC-MCM8PLUS
U35 = PCA9555_1: CLABCONF0: = SBC-MCM8PLUS
U58 U59 = ATA6563: CLABCONF0: = SBC-MCM8PLUS; P/N: 116A00380S
C51 = 100nF,_10V,_X7R,_10%,_0402_3: CLABCONF0: = SBC-MCM8PLUS
C52 = 10uF,6.3V,0603,20%X5R: CLABCONF0: = SBC-MCM8PLUS
C278 = 1uF,X5R,6.3V,0402: CLABCONF0: = SBC-MCM8PLUS; P/N: 151D10510S
D7 = ZENER_24V_500mW_SOD-123: CLABCONF0: DNP
L8 = INC_DELTA_SI43-100,_10uH: CLABCONF0: = SBC-MCM8PLUS; CLABCONF1: <null>
L59-L63 = ESD_CHOKE_DIFFx2_10: CLABCONF0: = SBC-MCM8PLUS; P/N: 142D11801S
P22 = FPC_Connector_0: CLABCONF0: = SBC-MCM8PLUS; P/N: 182P03002S
P45 = FPC_Connector_4: CLABCONF0: = SBC-MCM8PLUS; P/N: 182P00802S
R36 = 2.2R,5%,0402,1_16W: CLABCONF0: = SBC-MCM8PLUS; P/N: 161C00005S
R39 = 2.2R,5%,0402,1_16W_1: CLABCONF0: = SBC-MCM8PLUS; P/N: 161C06R25S
R41 = 0R,_0402_5: CLABCONF0: = SBC-MCM8PLUS
R75 = 2.2K,5%,0402.1_16W: CLABCONF0: = SBC-MCM8PLUS
R83 = 0R,_0402_2: CLABCONF0: = SBC-MCM8PLUS
R138 = 0R,_0402_4: CLABCONF0: = SBC-MCM8PLUS
R211 = 0R,_0402_3: CLABCONF0: DNP
R221 R294 = 0R,_0402: CLABCONF0: = SBC-MCM8PLUS
R229 = 10K,1%,0402,1_16W_0: CLABCONF0: = SBC-MCM8PLUS
U15 = AIC1647_0: CLABCONF0: = SBC-MCM8PLUS; P/N: 123C40000S
U32 = IP4220CZ6_0: CLABCONF0: = SBC-MCM8PLUS
C59 = 100nF,_10V,_X7R,_10%,_0402_1: CLABCONF0: = SBC-MCM8PLUS; P/N: 151B10600S
C62 = 100nF,_10V,_X7R,_10%,_0402_2: CLABCONF0: = SBC-MCM8PLUS; P/N: 151B10600S
C223 = 10nF,_25V,_X7R,_10%,_0402_2: CLABCONF0: = SBC-MCM8PLUS
C258 = 10nF,_25V,_X7R,_10%,_0402_3: CLABCONF0: = SBC-MCM8PLUS
C259 = 10nF,_25V,_X7R,_10%,_0402_4: CLABCONF0: = SBC-MCM8PLUS
C260 = 10nF,_25V,_X7R,_10%,_0402_5: CLABCONF0: = SBC-MCM8PLUS
C264 = 10nF,_25V,_X7R,_10%,_0402_6: CLABCONF0: = SBC-MCM8PLUS
C265 = 10nF,_25V,_X7R,_10%,_0402_1: CLABCONF0: = SBC-MCM8PLUS; P/N: 151B10600S
C837 C882-C885 = 100uF,_6.3V,_X5R,_20%,_1206: CLABCONF0: = SBC-MCM8PLUS
L11 L14 = Ferrit_330R-100Mhz,1.2A: CLABCONF0: = SBC-MCM8PLUS; P/N: 147D12102S
P9 = Conn.,_Mini-PCIe,_for_SIM5360: CLABCONF0: = SBC-MCM8PLUS; P/N: 182K05202S
P26 = uSIM_SOCKET_2: CLABCONF0: = SBC-MCM8PLUS; P/N: 190I01100S
R81 = 0R_3: CLABCONF0: DNP
R106 = 1M_,5%,_0402_2: CLABCONF0: = SBC-MCM8PLUS; P/N: 161C10021S
R206 = 1M_,5%,_0402: CLABCONF0: = SBC-MCM8PLUS; P/N: 161C10021S
R224 = 33R,5%,0402,1_16W_0_1: CLABCONF0: = SBC-MCM8PLUS; P/N: 161C27R41S
R236 = 33R,5%,0402,1_16W_0_2: CLABCONF0: = SBC-MCM8PLUS; P/N: 161C27R41S
R237 = 33R,5%,0402,1_16W_0_3: CLABCONF0: = SBC-MCM8PLUS; P/N: 161C27R41S
R257 = 33R,5%,0402,1_16W_0: CLABCONF0: = SBC-MCM8PLUS; P/N: 161C27R41S
R271 = 0R_6: CLABCONF0: DNP
R272 = 0R: CLABCONF0: = SBC-MCM8PLUS
R293 = 10K,1%,0402,1_16W: CLABCONF0: DNP
R295 = 0R,_0402_1: CLABCONF0: DNP
R296 = 0R,_0402_2: CLABCONF0: DNP
R298 = 10K,1%,0402,1_16W_1: CLABCONF0: DNP
R304 = 0R,_0402_3: CLABCONF0: = SBC-MCM8PLUS
R318 = 1M_,5%,_0402_1: CLABCONF0: = SBC-MCM8PLUS; P/N: 161C10021S
R322 = 0R_1: CLABCONF0: DNP
R331 = 0R_4: CLABCONF0: DNP
R334 = 0R_2: CLABCONF0: DNP
R335 = 0R_5: CLABCONF0: DNP
R336 = 0R_7: CLABCONF0: DNP
R337 = 0R_8: CLABCONF0: DNP
TP_nSIM_DET_SW = TP_SMT_0: CLABCONF0: DNP
U24 = 9FGV0241AKLF_6: CLABCONF0: = SBC-MCM8PLUS; EN: 301-0-01673; HEIGHT: 1MM; Temp_Range: -40C to +85&#8451;
BH1 = BATT_HOLDER_0: CLABCONF0: = SBC-MCM8PLUS
BT1 = BATT_2032: CLABCONF0: = SBC-MCM8PLUS
C80 = 10uF,6.3V,0603,20%,X5R_0: CLABCONF0: = SBC-MCM8PLUS
C130 = 100nF,_10V,_X7R,_10%,_0402_8: CLABCONF0: = SBC-MCM8PLUS; P/N: 151E22410S
C132 C142 C143 = 100nF,_10V,_X7R,_10%,_0402_0: CLABCONF0: = SBC-MCM8PLUS; Group: LAN2
C133 C134 C157 C162 = 22uF_25V: CLABCONF0: = SBC-MCM8PLUS; P/N: 151E10680S
C135 = 100nF,_10V,_X7R,_10%,_0402_9: CLABCONF0: = SBC-MCM8PLUS; P/N: 151B22610S
C136 = 100nF,_10V,_X7R,_10%,_0402: CLABCONF0: = SBC-MCM8PLUS; P/N: 151B22610S
C137 = 2.2nF,_50V,_X7R,_10%,_0402_2: CLABCONF0: = SBC-MCM8PLUS
C138 = 2.2nF,_50V,_X7R,_10%,_0402_4: CLABCONF0: DNP
C144 C150 = 22uF_25V: CLABCONF0: = SBC-MCM8PLUS; P/N: 151D10630S
C151 = 100nF,_10V,_X7R,_10%,_0402_1: CLABCONF0: = SBC-MCM8PLUS; P/N: 151B22610S
C152 = 2.2nF,_50V,_X7R,_10%,_0402_5: CLABCONF0: = SBC-MCM8PLUS
C153 = 100nF,_10V,_X7R,_10%,_0402_3: CLABCONF0: = SBC-MCM8PLUS; P/N: 151B22610S
C154 = 2.2nF,_50V,_X7R,_10%,_0402: CLABCONF0: DNP
C155 = 2.2nF,_50V,_X7R,_10%,_0402_1: CLABCONF0: DNP
C156 = 100nF,_10V,_X7R,_10%,_0402_5: CLABCONF0: = SBC-MCM8PLUS; P/N: 151B22610S
C163 = 100nF,_10V,_X7R,_10%,_0402_6: CLABCONF0: = SBC-MCM8PLUS; P/N: 151B22610S
C166 = 2.2nF,_50V,_X7R,_10%,_0402_3: CLABCONF0: = SBC-MCM8PLUS
C256 = 100nF,_10V,_X7R,_10%,_0402_4: CLABCONF0: = SBC-MCM8PLUS; P/N: 151B22610S
C257 = 100nF,_10V,_X7R,_10%,_0402_7: CLABCONF0: = SBC-MCM8PLUS; P/N: 151B22610S
C262 = 100nF,_10V,_X7R,_10%,_0402_2: CLABCONF0: DNP; P/N: 151B10400S
D6 = Diode_Shotky,5A,30V_0: CLABCONF0: = SBC-MCM8PLUS; P/N: 130E40001S
D8 = 1A_Schottky_Barrier_Rectifier_1: CLABCONF0: = SBC-MCM8PLUS; P/N: 132D10080S
DS1 = LED-GREEN_1206_2: CLABCONF0: = SBC-MCM8PLUS
E8 = HDR_1x2_100MIL_TH_JUMPER: CLABCONF0: = SBC-MCM8PLUS
E9 = HDR_1x2_100MIL_TH_JUMPER_1: CLABCONF0: = SBC-MCM8PLUS
FB1 = Ferrite_bead_,_30_Ohm@5A: CLABCONF0: = SBC-MCM8PLUS
FB2 = Ferrite_bead_,_30_Ohm@5A_1: CLABCONF0: = SBC-MCM8PLUS
J4 = DC_Jack_,5.5_2.5,10A,20V: CLABCONF0: = SBC-MCM8PLUS
L26 = IND_6.8uH_3.5A: CLABCONF0: = SBC-MCM8PLUS; P/N: 147A6R804S
L31 L32 = IND_6.8uH_3.5A: CLABCONF0: = SBC-MCM8PLUS; P/N: 147A6R802S
Q5 = DUAL_N-MOSFET,_0.5A_20V: CLABCONF0: = SBC-MCM8PLUS
R1 = RESISTOR: CLABCONF0: = SBC-MCM8PLUS; P/N: 161F00211S
R88 = 10K,1%,0402,1_16W_0: CLABCONF0: = SBC-MCM8PLUS; Group: Always; P/N: 161C10021S
R126 = 13.3K,_0402_tmp: CLABCONF0: = SBC-MCM8PLUS; P/N: 161C13321S
R146 = 1K,1%,0402,1_16W_2: CLABCONF0: = SBC-MCM8PLUS; Group: CAN
R147 = 2.37K_1%,_0402_2: CLABCONF0: = SBC-MCM8PLUS; P/N: 161C12421S
R154 R180 = 10.5K_1%,0402: CLABCONF0: = SBC-MCM8PLUS; P/N: 161C64921S
R161 = 2.37K_1%,_0402_1: CLABCONF0: = SBC-MCM8PLUS; P/N: 161C17821S
R164 R173 R176 R250 = 100K,_0402_0: CLABCONF0: = SBC-MCM8PLUS
R165 R209 R252 = 40.2k_1%: CLABCONF0: = SBC-MCM8PLUS; P/N: 161C28721S
R175 R251 = 100K,_0402_0: CLABCONF0: DNP
R247 R255 R261 = 100K,_0402_0: CLABCONF0: DNP; P/N: 161C47511S
R249 = 2.37K_1%,_0402: CLABCONF0: = SBC-MCM8PLUS; P/N: 161C17821S
R253 = 10.5K_1%,0402: CLABCONF0: = SBC-MCM8PLUS; P/N: 161C56221S
R254 = 1K,1%,0402,1_16W_1: CLABCONF0: = SBC-MCM8PLUS; Group: CAN
R260 = 1K,1%,0402,1_16W: CLABCONF0: = SBC-MCM8PLUS; Group: CAN
R278 = 0R,_0402: CLABCONF0: DNP
R280 = 47K,_0402: CLABCONF0: = SBC-MCM8PLUS; P/N: 161C68001S
R281 = 1.5K_1%,_0402: CLABCONF0: = SBC-MCM8PLUS
U16 U18 U19 = RT7272B,Converter,3A,36V: CLABCONF0: = SBC-MCM8PLUS; P/N: 123V30000S
U20 = RT9186A,LDO_,2.5-5_0.5V,500mA: CLABCONF0: = SBC-MCM8PLUS
U21 = SN74LVC1G17: CLABCONF0: = SBC-MCM8PLUS; P/N: 106D90000S

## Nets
1V8_EN: R260.2 R261.1 U20.4(EN)
1V8_FB: R88.1 R126.1 U20.6(ADJ)
1V8_PER: C63.1 C80.1 C189.2 C196.1 C209.1 C241.1 C243.1 C244.1 C245.1 C264.1 L11.2 L14.1 P10.6 P15.6(+1.5V_1) P15.28(+1.5V_2) P15.48(+1.5V_3) R72.1 R126.2 R131.2 R293.1 R298.2 U6.15(DVDD33) U6.21(DVDD33) U20.7(Vout1) U20.8(Vout2) U24.7(VDDDIG1.8) ; also on sheet 4 5 14 15
3V3_GPIO_EXT: C193.1 Q4.3(D) R69.1 U35.21(VDD)
3V3_PER: C59.2 C62.2 C79.1 C156.2 C163.2 C173.1 C177.1 C178.1 C180.1 C181.1 C182.1 C184.1 C185.1 C186.1 C190.1 C194.1 C231.1 C232.1 C233.1 C239.2 C240.1 C242.1 C367.1 C373.1 C793.1 C837.2 C882.2 C883.2 C884.2 C885.2 C887.1 C889.1 L32.2 P9.2(+3.3V_AUX) P9.39(3.3V_AUX) P9.41(3.3V_AUX) P9.52(+3.3V_AUX) P10.4 P15.2(+3.3V_1) P15.39(RSVD6) P15.41(RSVD7) P15.52(+3.3V_2) P25.2(VCC) P45.3 Q4.2(S) R18.1 R40.1 R42.1 R43.2 R53.2 R69.2 R77.2 R78.2 R83.2 R106.2 R112.2 R138.1 R159.2 R166.2 R167.2 R169.1 R206.2 R210.1 R214.1 R215.1 R216.1 R219.1 R220.1 R235.1 R253.1 R318.2 U6.6(AVDD33) U6.37(DVDD33) U6.41(AVDD33) U6.44(VDDREG) U6.45(VDDREG) U11.14(VCC) U20.1(Vin1) U20.2(Vin2) U32.5(VBUS) U58.5(VIO) U59.5(VIO) ; also on sheet 2 3 4 5 6 7 14 15 16
5V0_PER: C135.2 C136.2 C183.1 C368.2 C371.2 C886.1 C888.1 L31.2 P10.2 P15.44(LED_WLAN#) R180.1 U58.3(VCC) U59.3(VCC) ; also on sheet 6 7 14 16
GND: BH1.1(MINUS) C50.2 C51.2 C52.2 C53.2 C54.1 C59.1 C60.2 C61.2 C62.1 C63.2 C66.2 C68.2 C79.2 C80.2 C130.2 C133.2 C134.2 C135.1 C136.1 C138.2 C144.2 C150.2 C151.1 C153.1 C154.2 C155.2 C156.1 C157.2 C162.2 C163.1 C173.2 C177.2 C178.2 C179.2 C180.2 C181.2 C182.2 C183.2 C184.2 C185.2 C186.2 C187.1 C188.2 C189.1 C190.2 C192.1 C193.2 C194.2 C195.1 C196.2 C199.2 C201.2 C203.2 C209.2 C218.2 C219.2 C223.2 C230.2 C231.2 C232.2 C233.2 C234.1 C235.1 C236.2 C237.2 C238.2 C239.1 C240.2 C241.2 C242.2 C243.2 C244.2 C245.2 C256.1 C257.1 C258.2 C259.2 C260.2 C261.2 C262.2 C263.2 C264.2 C265.2 C278.2 C367.2 C368.1 C371.1 C373.2 C760.2 C761.2 C793.2 C837.1 C882.1 C883.1 C884.1 C885.1 C886.2 C887.2 C888.2 C889.2 D8.ANODE DS1.CATHODE J4.2(R) J4.SH1 J4.SH2 J4.SH3 J4.SH4 L59.5(GND) L59.6(GND) L60.5(GND) L60.6(GND) L61.5(GND) L61.6(GND) L62.5(GND) L62.6(GND) L63.5(GND) L63.6(GND) P4.3 P6.S1(SHIELD) P6.S2(SHIELD) P7.4 P7.6 P9.4(GND) P9.9(GND) P9.15(GND) P9.18(GND) P9.21(GND) P9.26(GND) P9.27(GND) P9.29(GND) P9.34(GND) P9.35(GND) P9.37(GND) P9.40(GND) P9.43(GND) P9.50(GND) P10.9 P12.7 P12.8 P13.5 P13.6 P15.4(GND7) P15.9(GND1) P15.15(GND2) P15.18(GND8) P15.21(GND3) P15.26(GND9) P15.27(GND4) P15.29(GND5) P15.34(GND10) P15.35(GND6) P15.37(RSVD5) P15.40(GND11) P15.50(GND12) P18.5 P18.6 P19.5 P19.6 P21.5 P22.6 P22.9 P22.12 P22.15 P22.18 P22.21 P22.22 P22.24 P22.29 P22.30 P22.NC1 P22.NC2 P25.1(GND) P25.4(NC) P25.5(NC) P26.GND P27.1(SHIELD) P27.3(SHIELD) P27.4(SHIELD) P45.1 P45.8 P45.NC1 P45.NC2 Q1.1(S) Q5.1(S1) Q5.4(S2) Q29.1(S) Q29.4(S) R34.1 R35.2 R36.2 R46.2 R47.2 R51.1 R75.2 R86.2 R88.2 R97.2 R109.1 R110.1 R111.1 R113.1 R114.1 R147.2 R161.2 R164.2 R165.2 R176.2 R209.2 R249.2 R250.2 R252.2 R294.1 R321.1 R325.1 RN17.2(RB1) RN17.3(RC1) RN17.4(RD1) U6.47(GND) U6.49(GND) U11.7(GND) U15.2(GND) U16.4(GND) U16.9(PAD) U18.4(GND) U18.9(PAD) U19.4(GND) U19.9(PAD) U20.5(GND) U20.9(EPAD) U21.3(GND) U24.5(GNDREF) U24.6(GNDDIG) U24.10(GND_1) U24.12(~{OE0}) U24.15(GNDA) U24.19(~{OE1}) U24.21(GND_2) U24.24(GNDXTAL) U24.25(EPAD) U32.2(GND) U35.9(VSS) U35.25(CPAD) U58.2(GND) U59.2(GND) X4.2 X4.4 X7.2 X7.4 ; also on sheet 1 2 3 4 5 6 7 14 15 16
V3V3_BOOT: C143.1 U19.2(BOOT)
V3V3_COMP: C155.1 C166.1 U19.6(COMP)
V3V3_COMP_C: C166.2 R252.1
V3V3_EN: R251.1 R254.2 R255.1 U19.3(EN)
V3V3_FB: R249.1 R253.2 U19.5(FB)
V3V3_RLIM: R250.1 U19.7(RLIM)
V3V3_SW: C143.2 L32.1 U19.1(SW)
V5_BOOT: C132.1 U18.2(BOOT)
V5_COMP: C137.1 C138.1 U18.6(COMP)
V5_COMP_C: C137.2 R209.1
V5_FB: R147.1 R180.2 U18.5(FB)
V5_RLIM: R176.1 U18.7(RLIM)
V5_SW: C132.2 L31.1 U18.1(SW)
V5V0_EN: R146.2 R175.1 R247.1 U18.3(EN)
VCC_RTC: E9.1 ; also on sheet 3
A_IN: C48.2 R32.2
AMP_IN: R31.2 R32.1 U11.3(I)
AMP_OUT: R31.1 U11.1(I) U11.4(12)
AMP_SPDIF_RX: R139.2 U11.2(12)
AUD_nINT/SAI3_RXFS: P15.8(UIM_PWR) ; also on sheet 2
AUDIO_IN_DIG: C48.1 C68.1 P27.2(CENTER) R34.2
AUDIO_OUT_DIG: C50.1 P25.3(IN) R33.2 R35.1
CAN1_CAP: C760.1 R332.1 R333.2
CAN1_H: P4.1 R332.2 U58.7(CANH)
CAN1_L: P4.2 R333.1 U58.6(CANL)
CAN1_RX: R284.1 U58.4(RXD)
CAN1_RX/SAI2_TXC: R284.2 ; also on sheet 2
CAN1_STBY: R321.2 R342.2 U58.8(STBY)
CAN1_TX: R240.1 U58.1(TXD)
CAN1_TX/SAI2_RXC: R240.2 ; also on sheet 2
CAN2_CAP: C761.1 R343.1 R346.2
CAN2_H: P4.4 R343.2 U59.7(CANH)
CAN2_L: P4.5 R346.1 U59.6(CANL)
CAN2_RX: R289.1 U59.4(RXD)
CAN2_RX/SAI2_MCLK: R289.2 ; also on sheet 2
CAN2_STBY: R325.2 R347.2 U59.8(STBY)
CAN2_TX: R290.1 U59.1(TXD)
CAN2_TX/SAI2_TXD0: R290.2 ; also on sheet 2
CARRIER_3V3_GPIO0_0: R156.2 U35.1(I/O0.0)
CARRIER_3V3_GPIO0_1: R168.2 U35.2(I/O0.1)
CARRIER_3V3_GPIO0_2: R158.2 U35.3(I/O0.2)
CARRIER_3V3_GPIO0_3: R174.2 U35.4(I/O0.3)
CARRIER_3V3_GPIO0_4: R196.2 U35.5(I/O0.4)
CARRIER_3V3_GPIO0_5: R197.2 U35.6(I/O0.5)
CARRIER_3V3_GPIO0_6: R177.2 U35.7(I/O0.6)
CARRIER_3V3_GPIO0_7: R199.2 U35.8(I/O0.7)
CARRIER_3V3_GPIO1_0: R178.2 U35.10(I/O1.0)
CARRIER_3V3_GPIO1_1: R179.2 U35.11(I/O1.1)
CARRIER_3V3_GPIO1_2: R181.2 U35.12(I/O1.2)
CARRIER_3V3_GPIO1_3: R198.2 U35.13(I/O1.3)
CARRIER_3V3_GPIO1_4: R192.2 U35.14(I/O1.4)
CARRIER_3V3_GPIO1_5: R228.2 U35.15(I/O1.5)
CARRIER_3V3_GPIO1_6: R230.2 U35.16(I/O1.6)
CARRIER_3V3_GPIO1_7: R231.2 U35.17(I/O1.7)
CLGEN_DIF0N1: R236.2 U24.14(~{DIF0})
CLGEN_DIF0N2: R257.2 U24.18(~{DIF1})
CLGEN_DIF0P1: R224.2 U24.13(DIF0)
CLGEN_DIF0P2: R237.2 U24.17(DIF1)
CLGEN_SADR: R298.1 U24.4(SADR/REF1.8)
CSI1_B_FLASH_OUT: R181.1 ; also on sheet 5
CSI1_B_RST: R179.1 ; also on sheet 5
CSI1_B_TRG: R198.1 ; also on sheet 5
CSI1_PWR_DWN_B: R178.1 ; also on sheet 5
CSI2_B_FLASH_OUT: R231.1 ; also on sheet 4
CSI2_B_RST: R228.1 ; also on sheet 4
CSI2_B_TRG: R230.1 ; also on sheet 4
CSI2_PWR_DWN_B: R192.1 ; also on sheet 4
DC_IN: D8.CATHODE FB1.1 FB2.1 J4.1(CENTRAL)
DSI1_CN: L61.2 P22.13
DSI1_CP: L61.1 P22.14
DSI1_N0: L59.2 P22.7
DSI1_N1: L60.2 P22.10
DSI1_N2: L62.2 P22.16
DSI1_N3: L63.2 P22.19
DSI1_P0: L59.1 P22.8
DSI1_P1: L60.1 P22.11
DSI1_P2: L62.1 P22.17
DSI1_P3: L63.1 P22.20
DSI_BCKLIGHT_FB: D7.2(ANODE) R41.2 U15.3(FB)
DSI_BCKLIGHT_IN: C51.1 C52.1 L8.1 R210.2 R229.1 U15.6(IN)
DSI_DISP_IOVCC: C54.2 C188.1 P22.27 R83.1
DSI_DISP_RESET: P22.26 R75.1 R196.1
DSI_DISP_VCI: C53.1 C187.2 P22.28 R138.2
DSI_LED_A: C278.1 D2.CATHODE D7.1(CATHODE) P22.4 U15.5(OVP)
DSI_LED_EN: R211.2 R229.2 U15.4(EN/PWM)
DSI_LED_K: P22.2 R39.1 R41.1
DSI_TOUCH_RESET: R197.1 R221.1
DSI_TP_INT/SAI5_RXD1: P45.6 U32.3(IO2) ; also on sheet 3
DSI_WLD_RES: R36.1 R39.2
DSI_WLD_SW: D2.ANODE L8.2 U15.1(LX)
ECSPI1_MISO: P12.5 ; also on sheet 2
ECSPI1_MOSI: P12.3 ; also on sheet 2
ECSPI1_SCLK: P12.9 ; also on sheet 2
ECSPI1_SS0: P12.1 ; also on sheet 2
ECSPI2_MISO: P12.6 ; also on sheet 2
ECSPI2_MOSI: P12.4 ; also on sheet 2
ECSPI2_SCLK: P12.10 ; also on sheet 2
ECSPI2_SS0: P12.2 ; also on sheet 2
ENET1_EV0_IN/SAI1_RXFS: P15.43(RSVD8) ; also on sheet 2
ENET1_EV0_OUT/SAI1_RXC: P15.45(RSVD9) ; also on sheet 2
ENET1_EV1_IN/SAI1_RXD0: P15.47(RSVD10) ; also on sheet 2
ENET1_EV1_OUT/SAI1_RXD1: P15.46(LED_WPAN#) ; also on sheet 2
ENET1_MDC/SAI1_RXD2: P15.11(REFCLK-) ; also on sheet 2
ENET1_MDIO/SAI1_RXD3: P15.13(REFCLK+) ; also on sheet 2
ENET1_nINT/SAI3_TXFS: P15.3(RSVD1) ; also on sheet 2
ENET1_nRST/SAI3_TXC: P15.1(WAKE#) ; also on sheet 2
ENET1_nWOL/SAI3_TXD: P15.5(RSVD2) ; also on sheet 2
ENET1_RD0/SAI1_RXD4: P15.17(RSVD3) ; also on sheet 3
ENET1_RD1/SAI1_RXD5: P15.19(RSVD4) ; also on sheet 3
ENET1_RD2/SAI1_RXD6: P15.23(PER_N0) ; also on sheet 3
ENET1_RD3/SAI1_RXD7: P15.25(PER_P0) ; also on sheet 3
ENET1_RX_CTL/SAI1_TXFS: P15.33(PET_P0) ; also on sheet 3
ENET1_RX_ERR/SAI1_TXD6: P15.38(USB_D+) ; also on sheet 2
ENET1_RXC/SAI1_TXC: P15.31(PET_N0) ; also on sheet 3
ENET1_TD0/SAI1_TXD0: P15.20(RSVD18) ; also on sheet 3
ENET1_TD1/SAI1_TXD1: P15.22(PERST#) ; also on sheet 3
ENET1_TD2/SAI1_TXD2: P15.24(+3.3V_AUX) ; also on sheet 3
ENET1_TD3/SAI1_TXD3: P15.36(USB_D-) ; also on sheet 3
ENET1_TX_CLK/SAI1_MCLK: P15.42(LED_WWAN#) ; also on sheet 2
ENET1_TX_CTL/SAI1_TXD4: P15.32(SMB_DATA) ; also on sheet 3
ENET1_TX_ERR/SAI1_TXD7: R234.2 ; also on sheet 2 16
ENET1_TXC/SAI1_TXD5: P15.30(SMB_CLK) ; also on sheet 3
ENET_INT/GPIO1_11: R96.2 ; also on sheet 2
ENET_MDC: U6.30(MDC) ; also on sheet 3
ENET_MDIO: R131.1 U6.31(MDIO) ; also on sheet 3
ENET_nRST/GPIO1_10: R98.2 ; also on sheet 2
ENET_RD0: R18.2 U6.14(RXD0/SELRGV) ; also on sheet 3
ENET_RD1: R112.1 R113.2 U6.16(RXD1/TXDLY) ; also on sheet 3
ENET_RD2: R42.2 U6.17(RXD2/AN0) ; also on sheet 3
ENET_RD3: R40.2 U6.18(RXD3/AN1) ; also on sheet 3
ENET_RX_CTL: R43.1 R111.2 U6.13(RXCTL//PHY_AD2) ; also on sheet 3
ENET_RXC: R29.1 ; also on sheet 3
ENET_TD0: U6.23(TXD0) ; also on sheet 3
ENET_TD1: U6.24(TXD1) ; also on sheet 3
ENET_TD2: U6.25(TXD2) ; also on sheet 3
ENET_TD3: U6.26(TXD3) ; also on sheet 3
ENET_TX_CTL: U6.27(TXCTL) ; also on sheet 3
ENET_TXC: U6.22(TXCLK) ; also on sheet 3
ENET_VIO: P10.8 ; also on sheet 3
ENET_WOL/GPIO1_13: R95.2 ; also on sheet 2
ENT_MDI_N0: P6.P2(MDI0-) U6.2(MDIN0)
ENT_MDI_N1: P6.P4(MDI1-) U6.5(MDIN1)
ENT_MDI_N2: P6.P8(MDI2-) U6.8(MDIN2)
ENT_MDI_N3: P6.P10(MDI3-) U6.11(MDIN3)
ENT_MDI_P0: P6.P1(MDI0+) U6.1(MDIP0)
ENT_MDI_P1: P6.P3(MDI1+) U6.4(MDIP1)
ENT_MDI_P2: P6.P7(MDI2+) U6.7(MDIP2)
ENT_MDI_P3: P6.P9(MDI3+) U6.10(MDIP3)
ETH0_CT1: C60.1 C61.1 P6.P5(CT)
ETH0_G_LED_C: P6.P11(LED1_C) R46.1
ETH0_LED_ACT: P6.P12(LED1_A) R53.1 R114.2 U6.34(LED0/PHY_AD0)
ETH0_LINK-LED_10_100: D1.1(ANODE1) R109.2 R132.2 U6.35(LED1/PHY_AD1)
ETH0_LINK-LED_1000: D1.2(ANODE2) R110.2 U6.32(LED2/RXDLY)
ETH0_Y_LED_A: D1.3(CATHODE) P6.P14(LED2_A) R132.1
ETH0_Y_LED_C: P6.P13(LED2_C) R47.1
ETH1_CT2: C66.1 P6.P6(CT)
EXP_nPWREN: Q29.2(G) R84.2 R86.1
EXP_nPWREN_G: Q4.1(G) Q29.6(D) R77.1
EXP_RST/GPIO1_08: P19.4 R84.1 ; also on sheet 2
EXPANDER_A0: R166.1 RN17.5(RD2) U35.18(A0)
EXPANDER_A1: R167.1 RN17.6(RC2) U35.23(A1)
EXPANDER_A2: R159.1 RN17.7(RB2) U35.24(A2)
EXT_NVCC_SNVS_1P8: P10.10 ; also on sheet 2
GBEPHY1_CLK_XIN: C234.2 U6.42(CKXTAL1) X4.1
GBEPHY1_CLK_XOUT: C235.2 U6.43(CKXTAL2) X4.3
GEN_I2C_SCL: R295.2 U24.8(SCLK_3.3)
GEN_I2C_SDA: R296.2 U24.9(SDATA_3.3)
GPIO1_00: P19.1 R342.1 ; also on sheet 2
GPIO1_01: P19.3 R347.1 ; also on sheet 2
GPIO1_05: P19.7 ; also on sheet 2
GPIO1_06: P19.9 ; also on sheet 2
GPIO1_15: P19.8 ; also on sheet 2
GPIO2_19/SD2_RESET_B: P21.3 ; also on sheet 3
GPIO3_23/SAI5_RXD2: P21.7 ; also on sheet 2
GPIO3_24/SAI5_RXD3: P21.9 ; also on sheet 2
GPIO4_21/SAI2_RXFS: P21.2 ; also on sheet 2
GPIO4_23/SAI2_RXD0: P21.4 ; also on sheet 2
GPIO4_24/SAI2_TXFS: P21.6 ; also on sheet 2
GPIO5_20/I2C4_SCL: P21.8 R271.2 ; also on sheet 2
GPIO5_21/I2C4_SDA: P21.10 R81.2 ; also on sheet 2
I2C3_SCL: P18.7 R133.1 ; also on sheet 2
I2C3_SDA: P18.9 R99.1 ; also on sheet 2
I2C5_SCL/SAI5_RXD0: P18.4 P45.4 U32.6(IO4) ; also on sheet 2 5
I2C5_SDA/SAI5_MCLK: P18.2 P45.5 U32.4(IO3) ; also on sheet 2 5
I2C6_SCL/SAI5_RXFS: P18.8 ; also on sheet 2
I2C6_SDA/SAI5_RXC: P18.10 ; also on sheet 2
INT_EXP: R234.1 R235.2 U35.22(\\~{IN}T)
J_MOD_8: P7.8 R155.2
JTAG_HDR_2: P7.2 R130.2
JTAG_HDR_10: P7.10 R51.2
JTAG_MOD: R155.1 ; also on sheet 3
JTAG_POWER: C192.2 D14.ANODE R72.2 R78.1 R130.1 R362.1 R363.1
JTAG_RST: D10.CATHODE P7.9 R330.2
JTAG_RST_PU: D14.CATHODE R330.1
JTAG_TCK: P7.3 ; also on sheet 3
JTAG_TDI: P7.7 R363.2 ; also on sheet 3
JTAG_TDO: P7.5 ; also on sheet 3
JTAG_TMS: P7.1 R362.2 ; also on sheet 3
LVDS_DISP_RESET: R177.1 ; also on sheet 7
LVDS_TOUCH_RESET: R199.1 ; also on sheet 7
MIPI_DSI1_CLK_N: L61.3 ; also on sheet 3
MIPI_DSI1_CLK_P: L61.4 ; also on sheet 3
MIPI_DSI1_D0_N: L59.3 ; also on sheet 3
MIPI_DSI1_D0_P: L59.4 ; also on sheet 3
MIPI_DSI1_D1_N: L60.3 ; also on sheet 3
MIPI_DSI1_D1_P: L60.4 ; also on sheet 3
MIPI_DSI1_D2_N: L62.3 ; also on sheet 3
MIPI_DSI1_D2_P: L62.4 ; also on sheet 3
MIPI_DSI1_D3_N: L63.3 ; also on sheet 3
MIPI_DSI1_D3_P: L63.4 ; also on sheet 3
MIPI_FPC_RES: P45.7 R221.2 U32.1(IO1)
mPCIE_45: P9.45(RSVD/PCM_CLK) R334.1
mPCIE_47: P9.47(RSVD/PCM_OUT) R335.1
mPCIE_49: P9.49(RSVD/PCM_IN) R336.1
mPCIE_51: P9.51(RSVD/PCM_SYNC) R337.1
mPCIE_CLKREQ#: P9.7(CLKREQ#/EAR1N) R106.1 R271.1 R304.1
mPCIe_PERST: R156.1 R272.2
mPCIE_REFCLKN: P9.11(REFCLK-/UART_CTS) R257.1
mPCIE_REFCLKP: P9.13(REFCLK+/UART_RTS) R237.1
mPCIE_RST#: P9.22(PERST#) R206.1 R272.1
mPCIE_SMB_DATA: P9.32(GPIO6/SMB_DATA) R322.2
mPCIE_SMB_SCL: P9.30(GPIO9/SMB_CLK) R331.2
mPCIE_USB3_SSRXN: R336.2 ; also on sheet 16
mPCIE_USB3_SSRXP: R337.2 ; also on sheet 16
mPCIE_USB3_SSTXN: R334.2 ; also on sheet 16
mPCIE_USB3_SSTXP: R335.2 ; also on sheet 16
mPCIE_USB_DN: P9.36(USB_D-) ; also on sheet 16
mPCIE_USB_DP: P9.38(USB_D+) ; also on sheet 16
mPCIE_WAKE#: P9.1(WAKE#/MIC1P) R81.1 R318.1
P15_I2C3_SCL: P15.14(UIM_RESET) R133.2
P15_I2C3_SDA: P15.16(UIM_VPP) R99.2
PCIE_CLGEN_PDN: Q1.6(D) U24.22(~{PD})
PCIE_CLGEN_SS_SEL: R293.2 R294.2 U24.23(SS_SEL_TRI)
PCIE_CLGEN_VDD1P8: C223.1 C258.1 C261.1 L11.1 U24.11(VDD1.8_1) U24.20(VDD1.8_2)
PCIE_CLGEN_VDDA_1P8: C259.1 C260.1 C265.1 L14.2 U24.3(VDDXTAL1.8) U24.16(VDDA1.8)
PCIE_CLGEN_X1_25: C219.1 U24.1(X1_25) X7.1
PCIE_CLGEN_X2: C218.1 U24.2(X2) X7.3
PCIE_REF_CLKN: R236.1 ; also on sheet 3
PCIE_REF_CLKP: R224.1 ; also on sheet 3
PCIE_RX_N: P9.23(PER_N0/NC) ; also on sheet 3
PCIE_RX_P: P9.25(PER_P0/NC) ; also on sheet 3
PCIE_TX_N: P9.31(PET_N0/NC) ; also on sheet 3
PCIE_TX_P: P9.33(PET_P0/NC) ; also on sheet 3
PHY0_ESWR: R220.2 U6.38(ENSWREG)
PHY0_INT: R96.1 R216.2 U6.20(INT)
PHY0_nRST: R98.1 R215.2 U6.29(PHYRSTB)
PHY0_PME: R95.1 R219.2 U6.33(PME)
PHY0_RXC: R29.2 U6.19(RXCLK)
PMIC_ON_REQ: P10.5 Q5.5(G2) ; also on sheet 2
PMIC_ON_REQn: Q5.2(G1) Q5.3(D2) R279.2
PMIC_STBY_REQ: P10.3 Q29.5(G) ; also on sheet 3
PWM1_OUT/SPDIF_EXT_CLK: R211.1 ; also on sheet 2
PWM2_OUT/SPDIF_RX: R139.1 ; also on sheet 2 7
PWR_CTRL: R146.1 R254.1 R260.1 R278.2 U21.4(Y)
PWR_CTRL_IN: Q5.6(D1) Q29.3(D) R277.2 R278.1 U21.2(A)
Q1_G1: Q1.2(G) R304.2
RGMII_AVDD_1P0: C195.2 C201.1 C203.1 C236.1 R76.1 U6.3(AVDD10) U6.9(AVDD10) U6.40(AVDD10)
RGMII_BIAS: R97.1 U6.39(RSET)
RGMII_LX: L10.1 U6.48(REG_OUT)
RGMII_VDD_1P0: C199.1 C230.1 C237.1 C238.1 L10.2 R76.2 U6.28(DVDD10) U6.36(DVDD10)
SAI3_MCLK: P15.12(UIM_CLK) ; also on sheet 2
SAI3_RXC/UART2_CTS: P15.10(UIM_DATA) ; also on sheet 2
SAI3_RXD/UART2_RTS: P15.7(CLKREQ#) ; also on sheet 2
SIM1_DET: P26.CD TP_nSIM_DET_SW.1
SIM_CLK: P9.12(UIM_CLK) P26.C3(CLK)
SIM_DATA: P9.10(UIM_DATA) P26.C7(IO)
SIM_PWR: C263.1 P9.8(UIM_PWR) P26.C1(VCC)
SIM_RST: P9.14(UIM_RESET) P26.C2(RST)
SIM_VPP: P9.16(UIM_VPP/GPIO42) P26.C6(VPP)
SPDIF_OUT1C: C49.1 R33.1
SPDIF_TX: C49.2 ; also on sheet 2
SYS_I2C_SCL: P18.3 R169.2 R295.1 U35.19(SCL) ; also on sheet 3 14
SYS_I2C_SDA: P18.1 R214.2 R296.1 U35.20(SDA) ; also on sheet 3 14
SYS_RST_PMIC: D10.ANODE P10.7 ; also on sheet 3
UART1_RXD: P13.3 ; also on sheet 2
UART1_TXD: P13.1 ; also on sheet 2
UART2_RXD: P13.9 ; also on sheet 3 14
UART2_TXD: P13.7 ; also on sheet 3 14
UART3_RXD: P13.4 ; also on sheet 2 14
UART3_TXD: P13.2 ; also on sheet 2 14
UART4_RXD: P13.10 ; also on sheet 3 14
UART4_TXD: P13.8 ; also on sheet 3 14
USB1_ID/GPIO1_07: P19.2 ; also on sheet 2 16
V_COIN: BH1.2(PLUS) C262.1 R281.1
V_SOM: C130.1 C151.2 C153.2 E8.1 P10.1 R1.2 R247.2 R255.2 R261.2 R277.1 R279.1 R280.1 U21.5(VCC) ; also on sheet 2 3
V_SOM_L: C256.2 C257.2 E8.2 L26.2 R1.1 R154.1
VCOIN: E9.2 R281.2
VDC_IN: C133.1 C134.1 C144.1 C150.1 C157.1 C162.1 D6.CATHODE D13.CATHODE R173.2 R175.2 R251.2 U16.8(VIN) U18.8(VIN) U19.8(VIN)
VDC_IN_5A: C179.1 D13.ANODE P15.49(RSVD11) P15.51(RSVD12)
VDCIN_FB: D6.ANODE FB1.2 FB2.2
VSOM_BOOT: C142.1 U16.2(BOOT)
VSOM_COMP: C152.1 C154.1 U16.6(COMP)
VSOM_COMP_C: C152.2 R165.1
VSOM_EN: R173.1 U16.3(EN)
VSOM_FB: R154.2 R161.1 U16.5(FB)
VSOM_LED: DS1.ANODE R280.2
VSOM_RLIM: R164.1 U16.7(RLIM)
VSOM_SW: C142.2 L26.1 U16.1(SW)
WLAN_PWR_DWN_B: R168.1 ; also on sheet 15

Not connected (* = marked no-connect by the designer): P9 3(COEX1/MIC1N)* 5(COEX2/EAR1P)* 6(+1.5V/NC)* 17(RSVD/UART_RXD)* 19(RSVD/UART_TXD)* 20(W_DISABLE#)* 24(+3.3V_AUX)* 28(+1.5V/NC)* 42(LED_WWAN#)* 44(LED_WLAN#/UART_RI)* 46(LED_WPAN#/UART_DTR)* 48(+1.5V/NC)*; P19 10*; P21 1*; P22 1* 3* 5* 23* 25*; P45 2*; R158 1; R174 1*; R322 1*; R331 1*; RN17 1(RA1)* 8(RA2)*; U6 12(NC)* 46(CLK125)*; U20 3(PGOOD)*

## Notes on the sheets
sheet 9
- ENET_QOS, RTL8211E Phy
- Enable internal delays
- TX delay is ENABLE
  RX delay is disable
- STRAPS
- MODE[1:0]
  11 ==> AUTO NEG ALL
  1.8V RGMII<-> SELRGV
- RTL8211E PHYSICAL ADDRESS: 100b
- PHYADDR0
- PHYADDR1
- PHYADDR2
- DNP
- Close to U6[37]
- SELRGV
- AN0
- DNP
- AN1
- TXDLY
- RXDLY
- DNP
- SILKSCREEN:
  ETH0
- Place near each
  AVDD10_ pin
- SELRGV
- AN0
- TXDLY
- 100 Ohm
- AN1
- 100 Ohm
- PHYADDRESS2
- 100 Ohm
- 100 Ohm
- RXDLY
- PHYADDRESS0
- PHYADDRESS1
- Ind2_5x2x1_2
- I2S for Audio CODEC or
  PHY_RST#/_INT#/_WOL#
- DNP
- SILKSCREEN: RGMII / I2S Extender
- PHY_RESET#
- ENET1, RGMII frontend
- PHY_INT#
- PHY_WOL#
- AUD_nINT
- High power traces (5A)
sheet 10
- JTAG
- FlexIO connectors
- NXP refdes layout
- DNP
- TMS
- VCC
- TCK
- GND
- TDO
- GND
- TDI
- SILKSCREEN:
- SILKSCREEN:
- GPIO1_00 -- GPIO1_07
  GPIO1_01 -- GPIO1_08
           GND -- GND
  GPIO1_05 -- GPIO1_15
  GPIO1_06 -- N/C
- N/C -- GPIO4_21
  GPIO2_19 -- GPIO4_23
           GND -- GPIO4_24
  GPIO3_23 -- GND
  GPIO3_24 -- GPIO5_21
- SILKSCREEN:
  JTAG
- I2C to GPIO expander
- DNP
- DNP
- SILKSCREEN:
- SILKSCREEN:
- V_SOM      -- 5V0_PER
  STBY_REQ -- 3V3_PER
  ON_REQ     -- 1V8_PER
  SYS_RST   -- ENET_VIO
          GND   --  EXT_SNVS_1V8
- ECSPI1 -- ECSPI2
- DNP
- DNP
- I2C Address:
  0x20
- SILKSCREEN:
- SILKSCREEN:
- I2C2_SDA  --  I2C5_SDA
  I2C2_SCL  --  I2C5_SCL
           GND --  GND
  I2C3_SCL  --  I2C6_SCL
  I2C3_SDA  --  I2C6_SDA
- UART1_TX  --  UART3_TX
  UART1_RX  --  UART3_RX
            GND  -- GND
  UART2_TX  --  UART4_TX
  UART2_RX  --  UART4_RX
- CAN Buses
- SPDIF
- SILKSCREEN:
  | CAN1+ | CAN1- | GND | CAN2+ | CAN2- |
- SILKSCREEN:
  Digital Audio IN
- Align with P4 Pin layout physical dimention
- DNP
- DNP
- SILKSCREEN:
  Digital Audio OUT
- DNP
sheet 11
- MIPI-DSI LCD connector
- MIPI-DSI LCD back-light power
- # 100-Ohm diff pairs
- Typical LED configuration: Two parallel chains of 6 serially connected LEDs
- DNP
- # 100-Ohm diff pairs
- SILKSCREEN:
  MIPI-DSI LCD
- MIPI-DSI touch-panel connector
- SILKSCREEN:
  MIPI-DSI Touch Ctl.
- Pinout of J5 reversed
   to FPC
- GT911 supports two I2C slave
  addresses: 0xBA/0xBB and 0x28/0x29.
  The host can select the address by
  changing the status of Reset and INT
  pins during the power-on
  initialization phase, refer:
  139D10080 Data Sheet, page 29
sheet 12
- mPCIE Connector
- nanoSIM
- DNP
- DNP
- # 85-Ohm differential pair
- SILKSCREEN:
  nanoSIM card
- # 85-Ohm differential pairs
- DNP
- DNP
- # 90-Ohm differential pairs
- # 90-Ohm differential pairs
- DNP
- SILKSCREEN:
  mPCIE Connector
- PCIe external clock
- I2C Address:
  0x68 (SADR=0, default, Int. PD)
  0x6A (SADR=1)
- # 85-Ohm differential pairs
- DNP
- DNP
- DNP
- DNP
- Configuration Straps
  PD#:        Internal PU (see spec)
  OE0#:       0 (Enable DIF0)
  OE1#:       0 (Enable DIF1)
  SS_SEL_TRI: 0 (SpreadSpect off)
- PD#: Input notifies device to sample
  latched inputs and start up on first
  high assertion. Low enters
  Power Down Mode, subsequent
  high assertions exit  Power Down Mode.
  This pin has internal pull-up resistor.
sheet 13
- POWER
- PWR_CTRL
- RTC battery
- DC input
- DNP
- DNP
- 3V3_PER
- 5V0_PER
- Power LED
- RLIM = 100k => ~4A
- DNP
- RLIM = 100k => ~4A
- DNP
- 1V8_PER
- V_SOM (3.7V, 3A)
- Current measure
- RLIM = 100k => ~4A
- DNP
